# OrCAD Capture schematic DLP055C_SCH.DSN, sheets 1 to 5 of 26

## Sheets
1 P25 - HARDWARE: rev: C
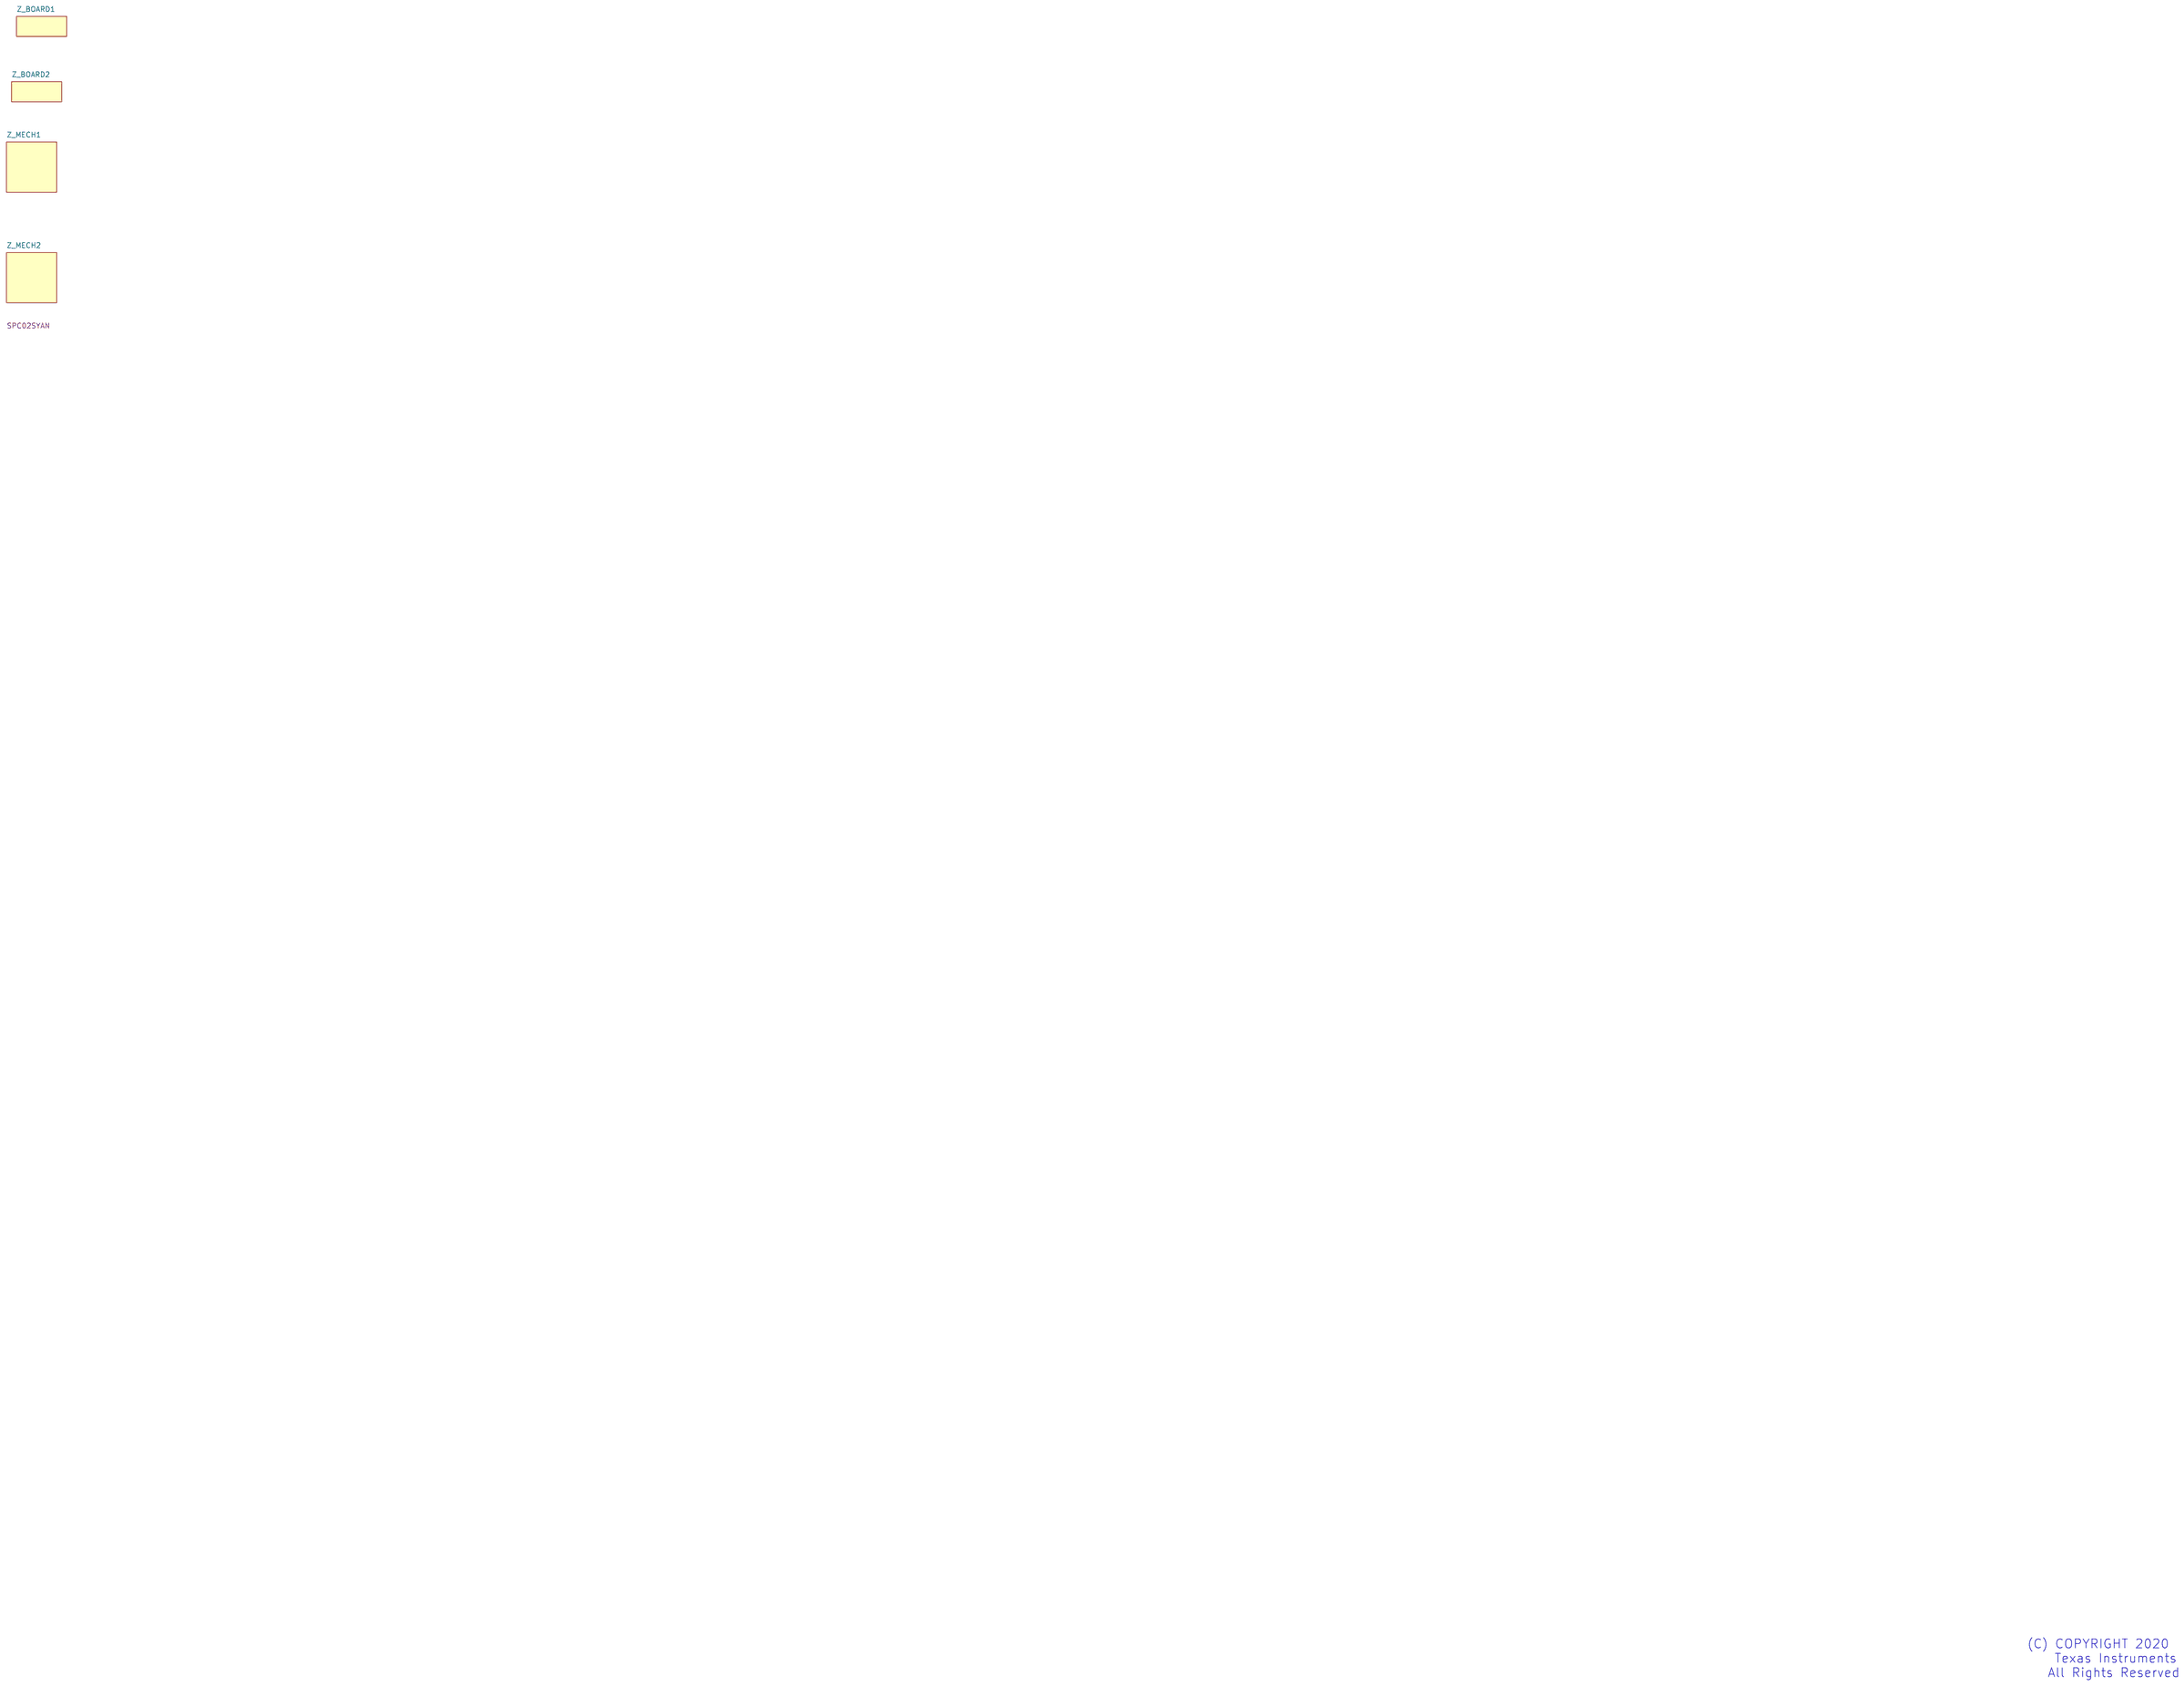
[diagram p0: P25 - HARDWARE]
2 P02 - REVISION HISTORY
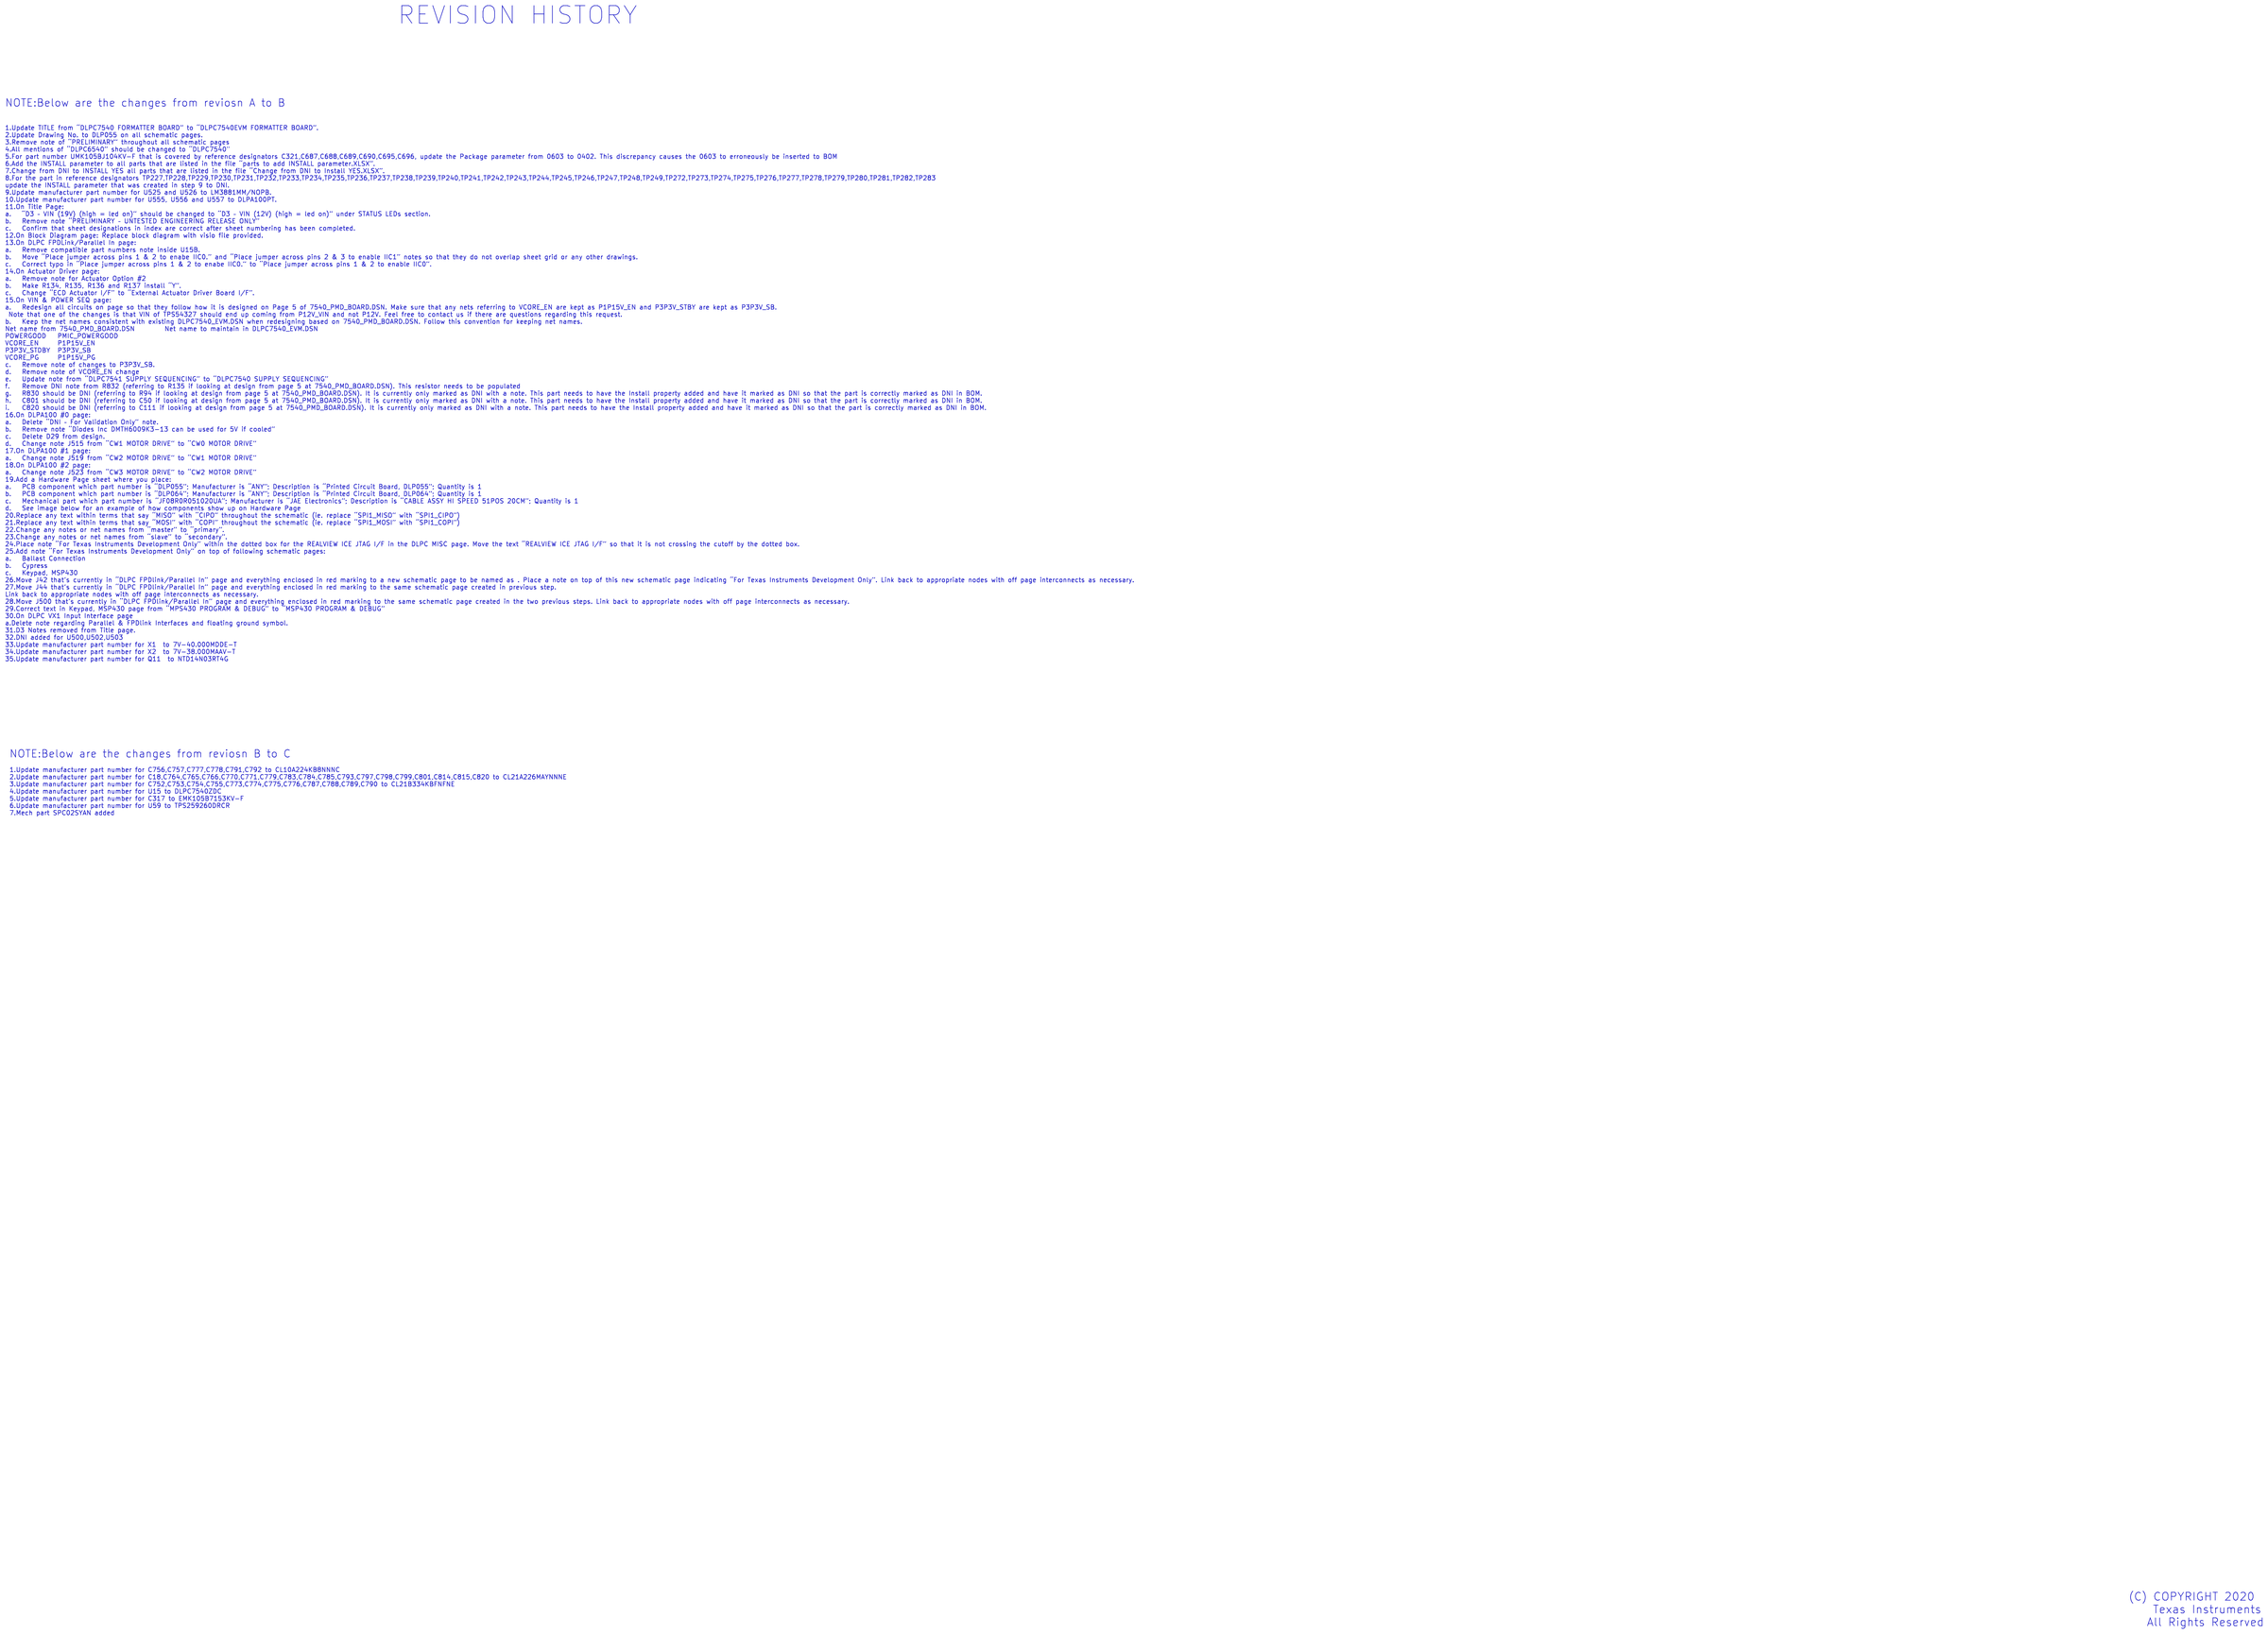
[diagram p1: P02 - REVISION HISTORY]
3 P24-FPDlink-Parallel In Connect: size C
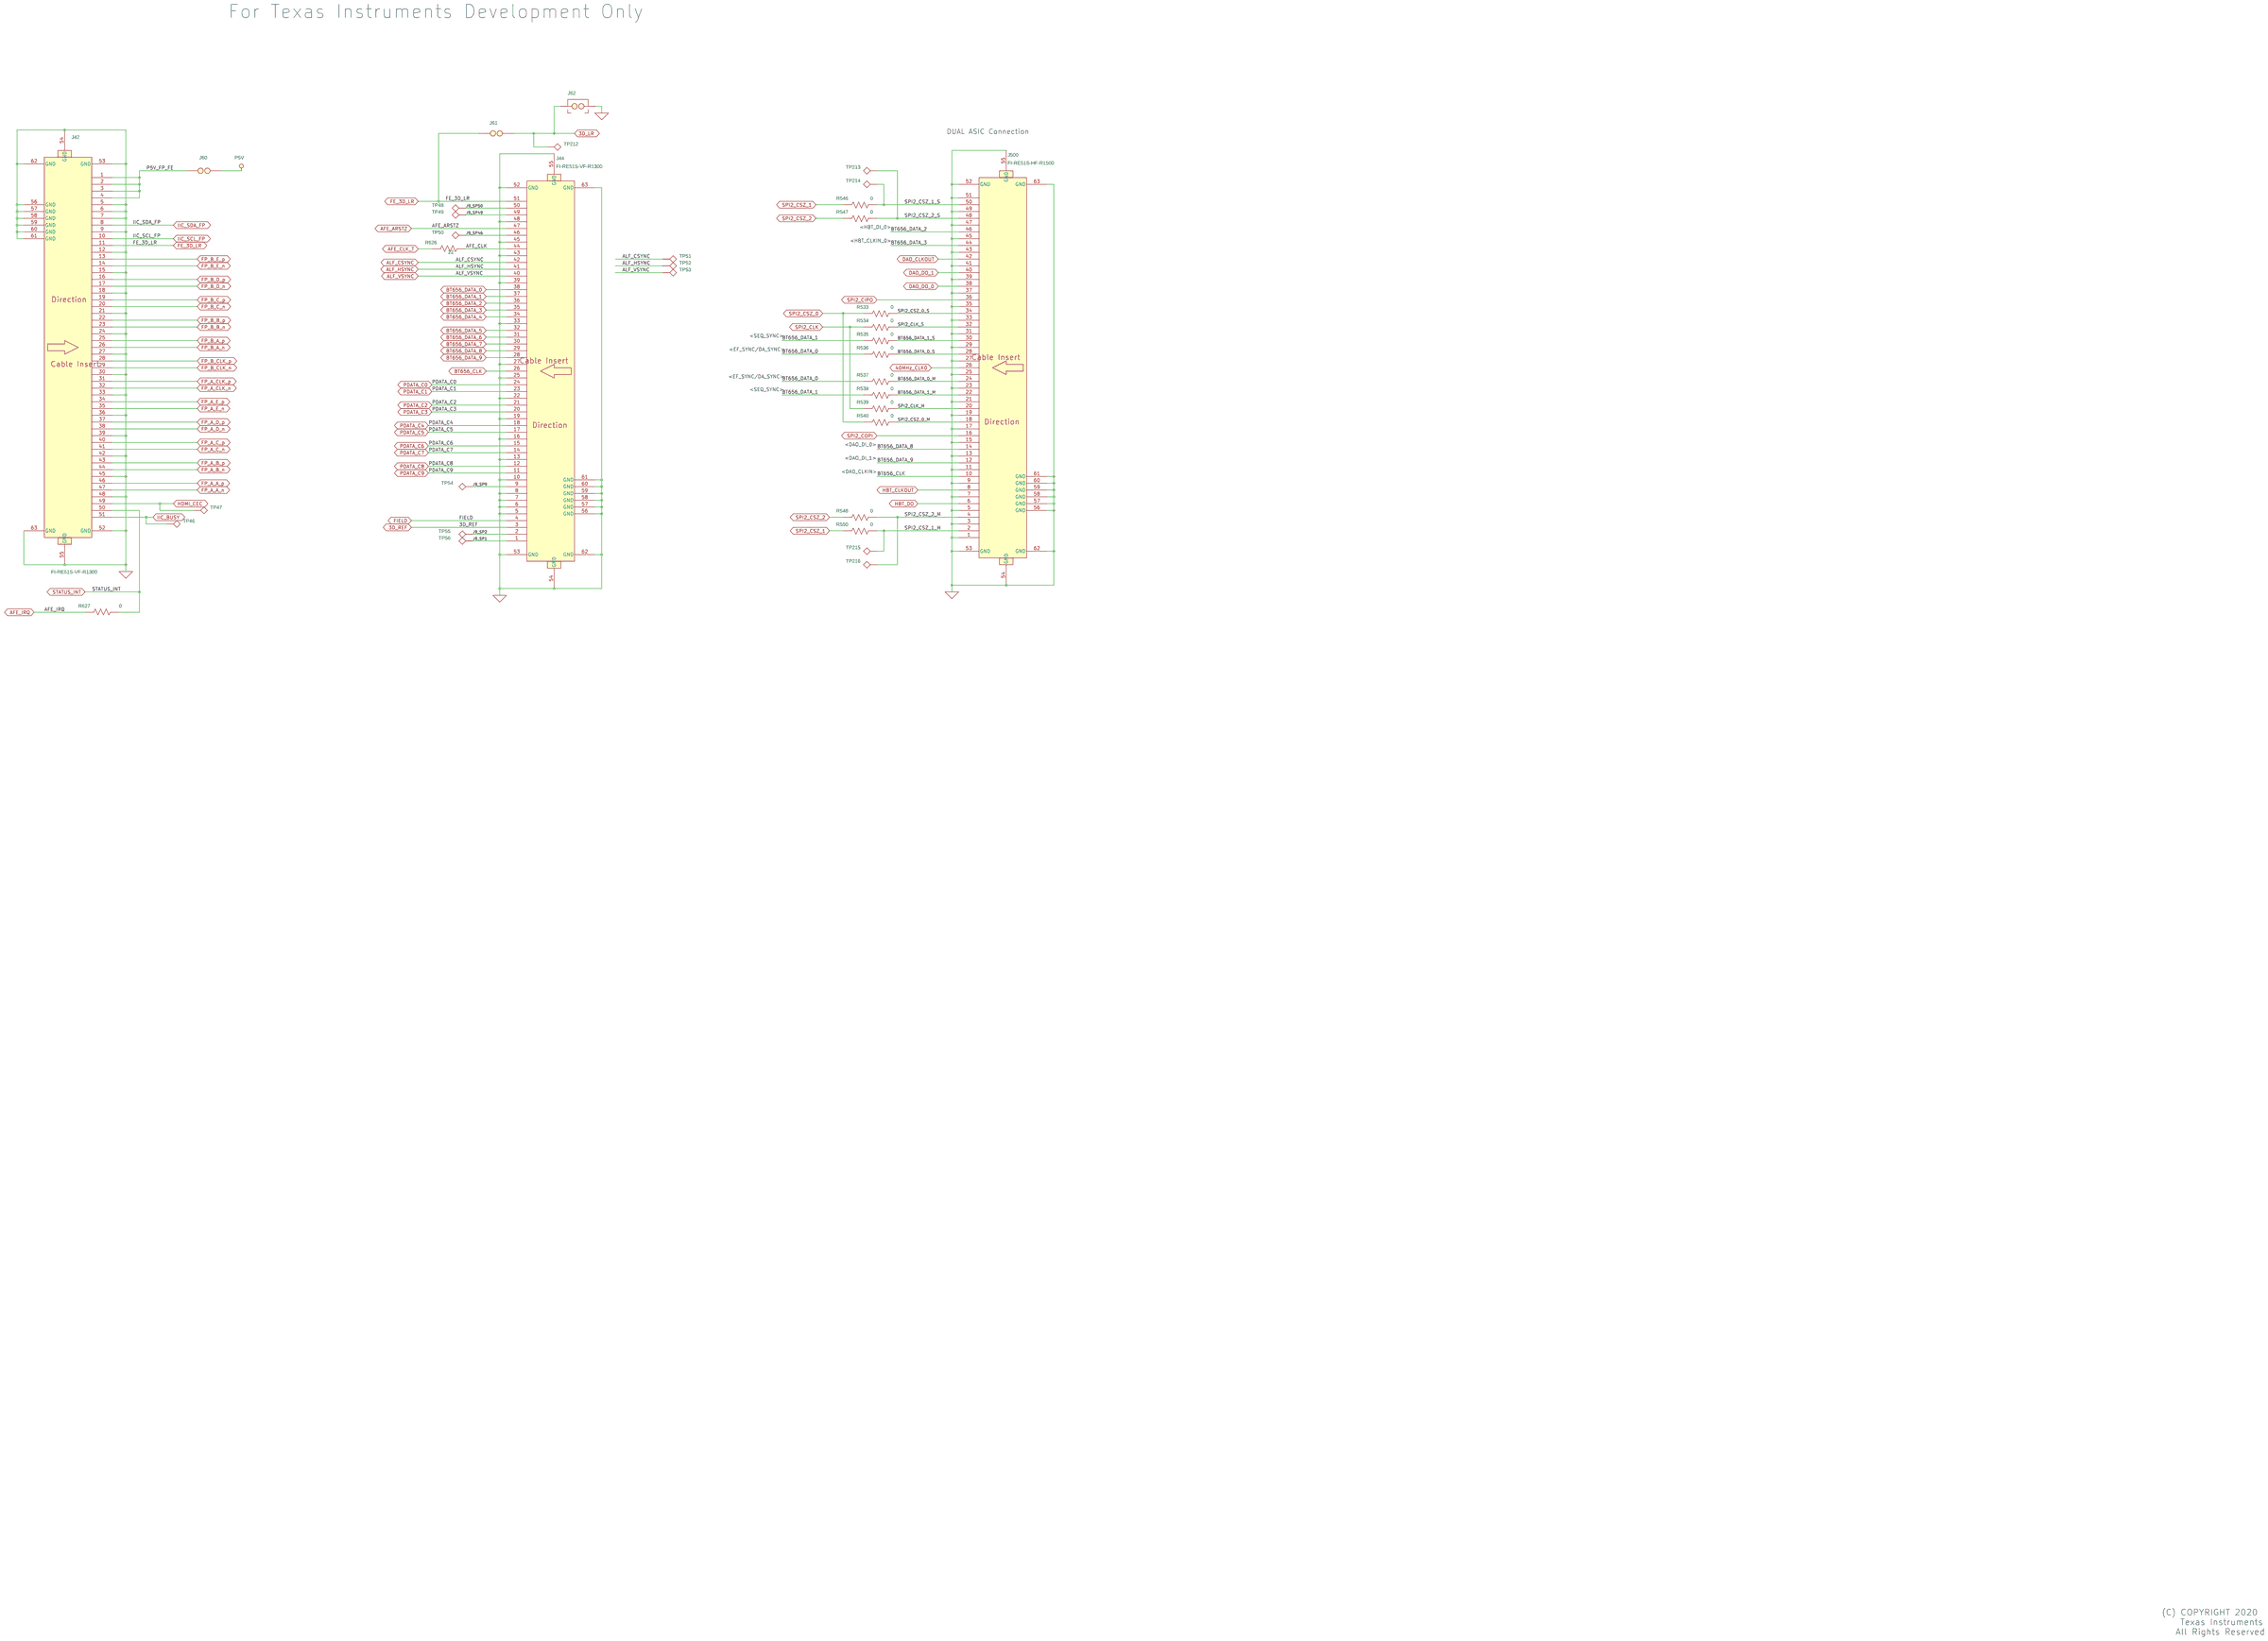
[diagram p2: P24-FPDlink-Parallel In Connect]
4 P22 - Cypress: size A3
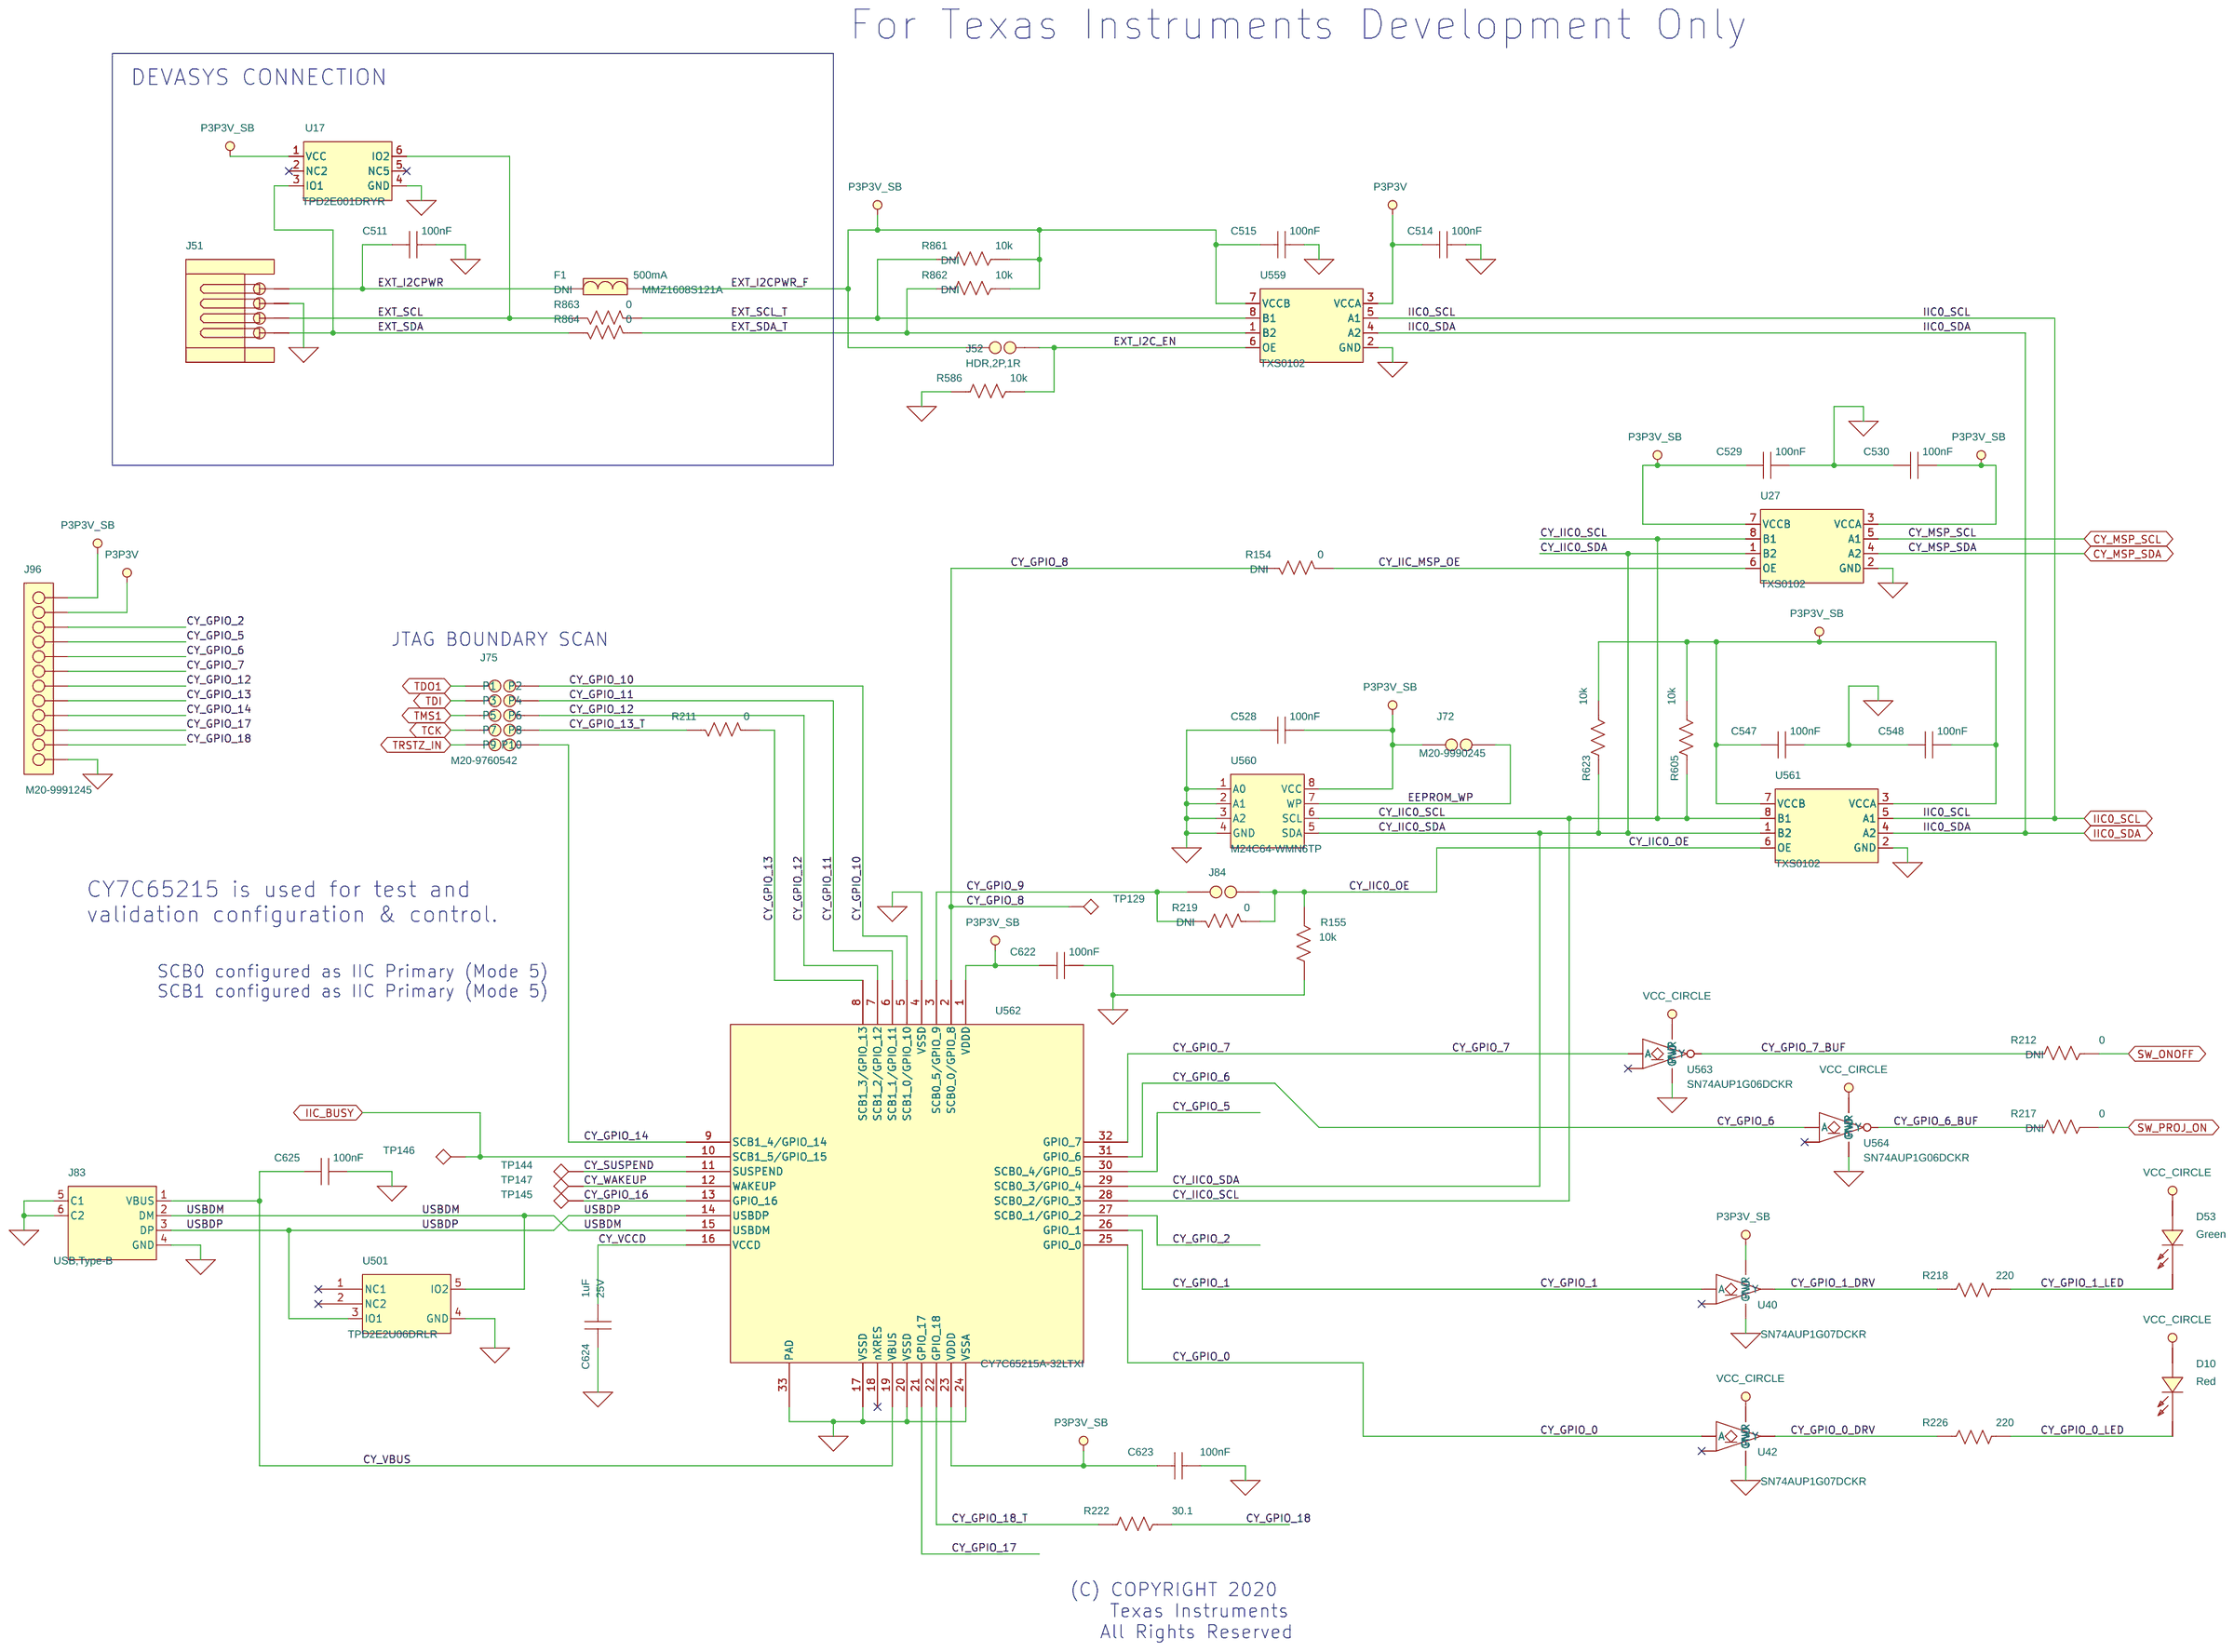
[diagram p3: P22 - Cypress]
5 P23 - Keypad, MSP430: size A3
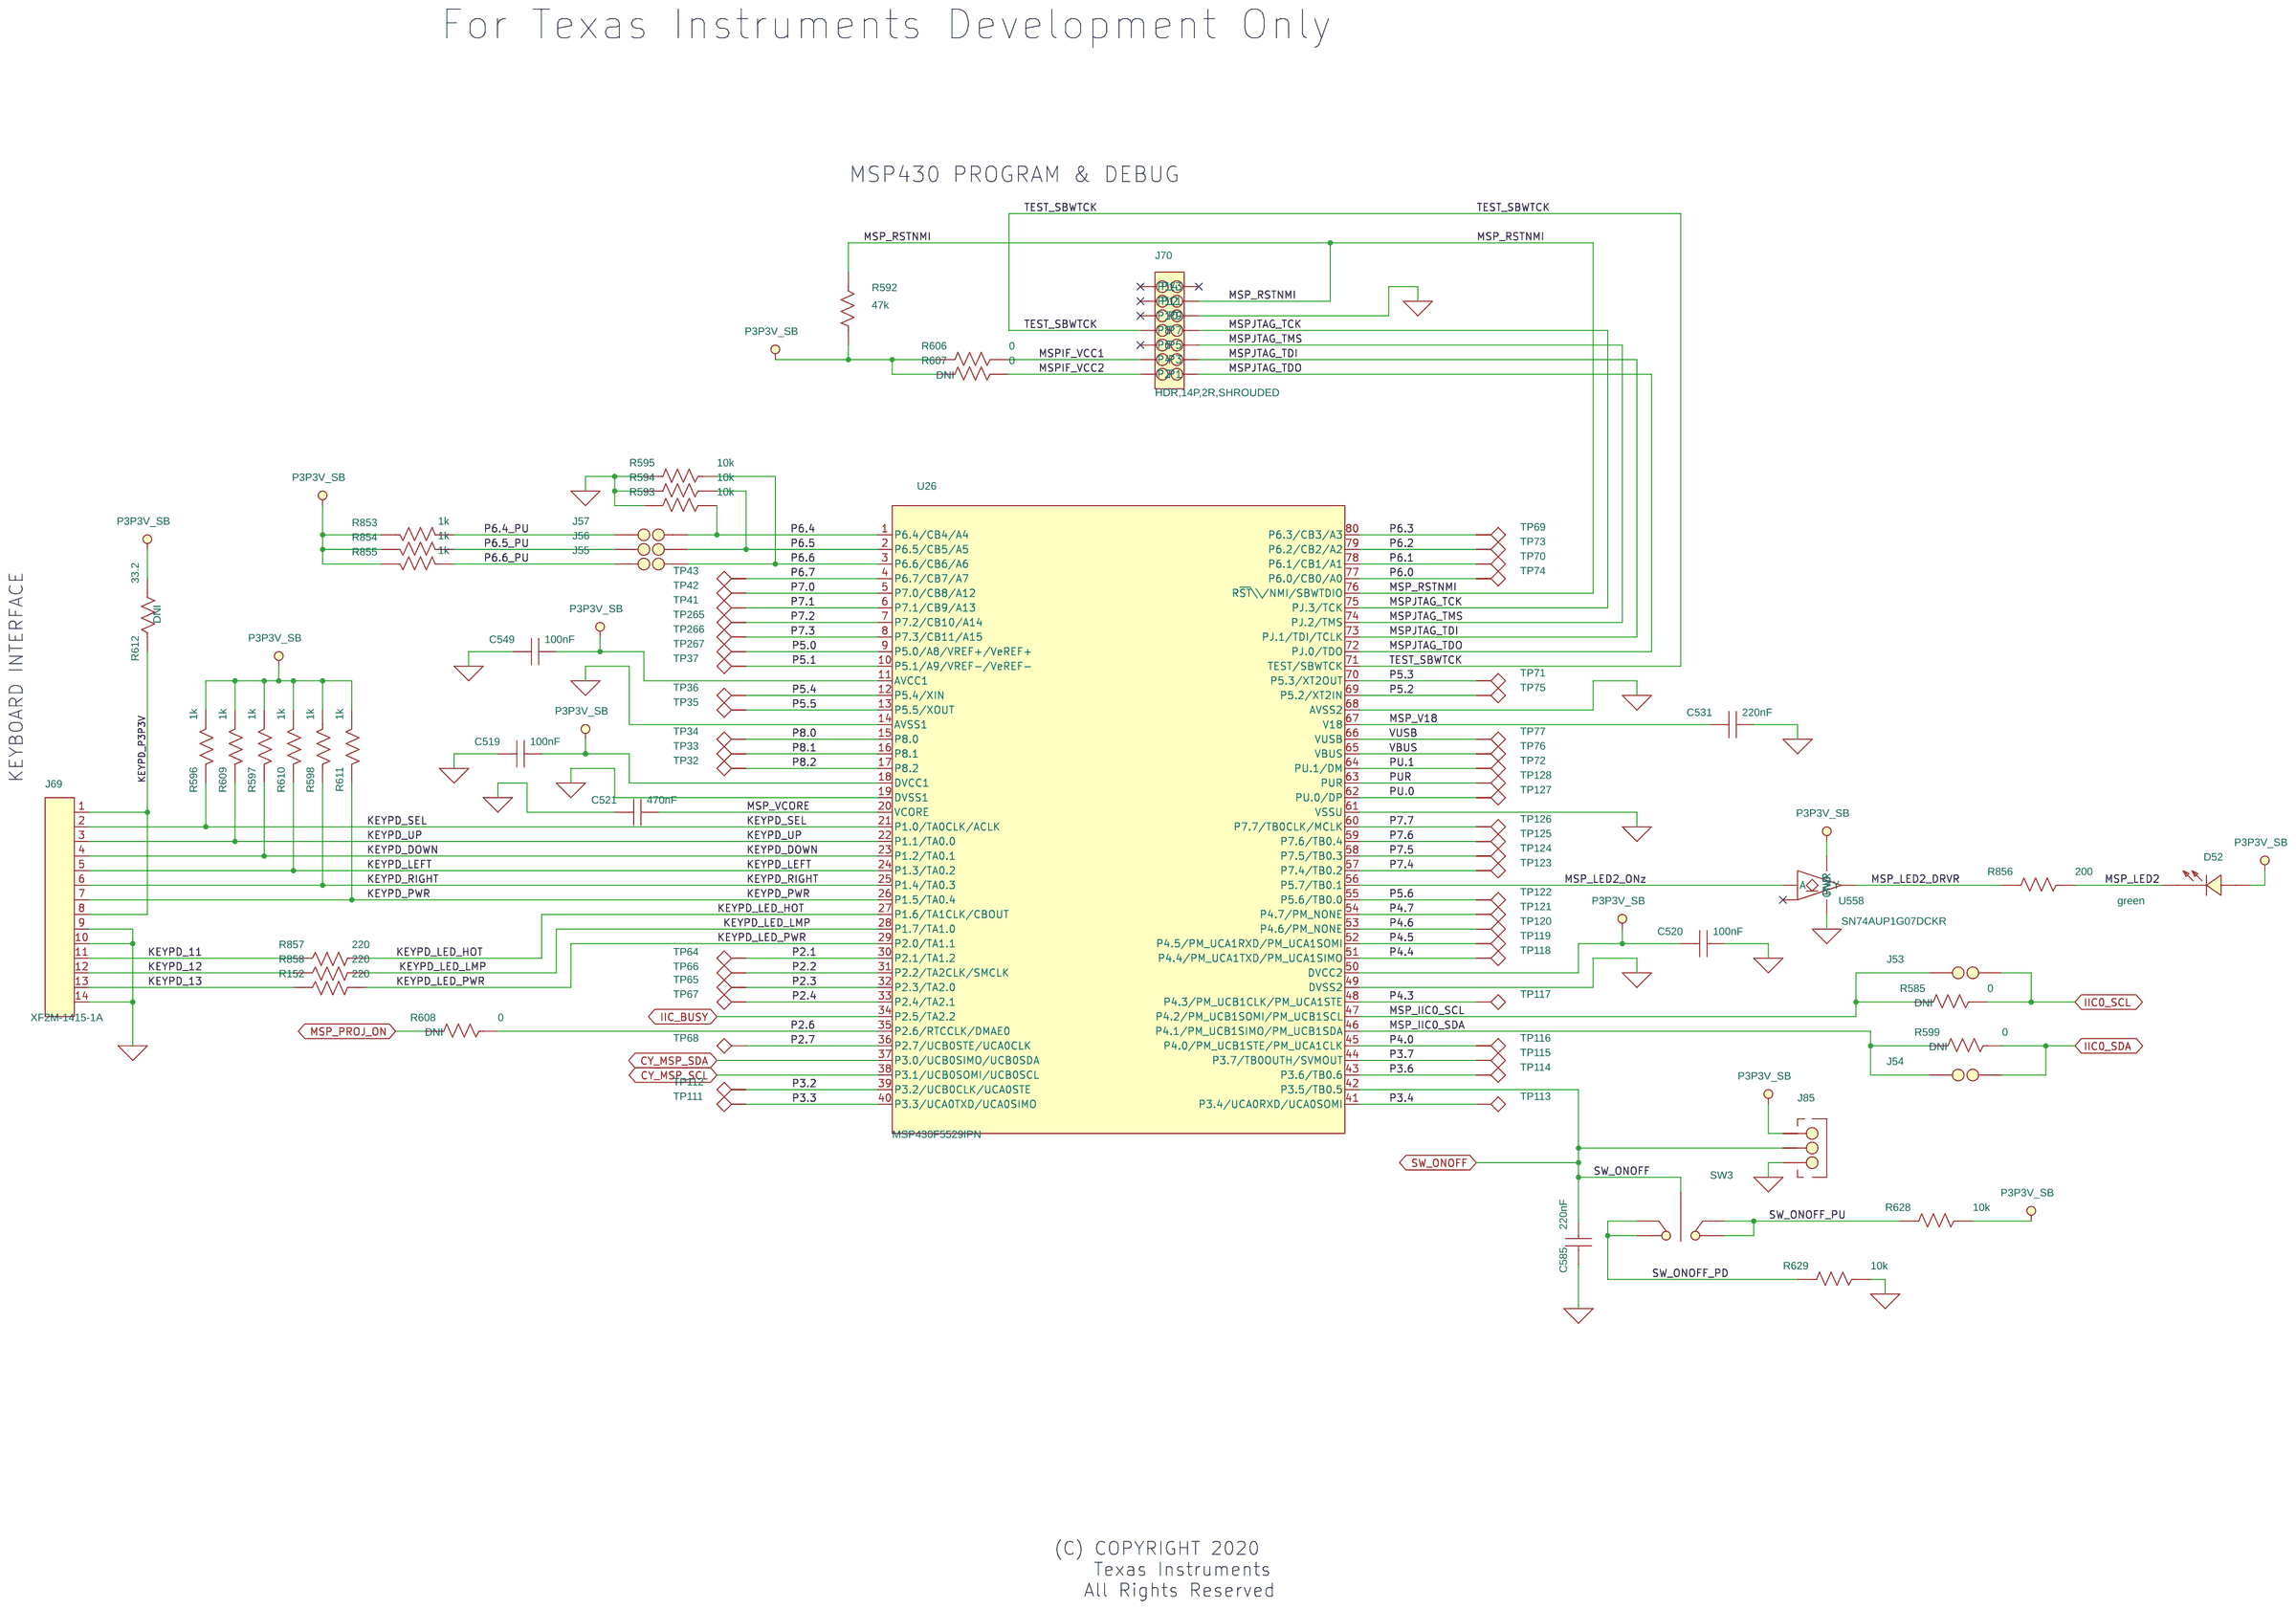
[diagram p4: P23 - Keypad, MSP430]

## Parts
sheet P22 - Cypress
C511  100nF  [0402]
C514  100nF  [0402]
C515  100nF  [0402]
C528  100nF  [0402]
C529  100nF  [0402]
C530  100nF  [0402]
C547  100nF  [0402]
C548  100nF  [0402]
C622  100nF  [0402]
C623  100nF  [0402]
C624  1uF  [0402]
C625  100nF  [0402]
D10  Red  [LED-LTST-C190_LITEON]
D53  Green  [LED-LTST-C190_LITEON]
F1  MMZ1608S121A  [0603]
J51  S4B-EH(LF)(SN)  [CONN4-S4BEH_JST]
J52  HDR,2P,1R  [HDR2P_1R]
J72  HDR,2P,1R  [HDR2P_1R]
J75  HDR,10P,2R  [HDR2X5]
J83  USB,Type-B  [CONN4-USB-897-43-004-90_MILL]
J84  HDR,2P,1R  [HDR2P_1R]
J96  HDR,12P,1R  [HDR1x12]
R154  0  [0402]
R155  10k  [0402]
R211  0  [0402]
R212  0  [0402]
R217  0  [0402]
R218  220  [0603]
R219  0  [0402]
R222  30.1  [0402]
R226  220  [0603]
R586  10k  [0402]
R605  10k  [0402]
R623  10k  [0402]
R861  10k  [0402]
R862  10k  [0402]
R863  0  [0402]
R864  0  [0402]
TP129  TP_WHT  [TP_Keystone_5011]
TP144  TP_WHT  [TP_Keystone_5011]
TP145  TP_WHT  [TP_Keystone_5011]
TP146  TP_WHT  [TP_Keystone_5011]
TP147  TP_WHT  [TP_Keystone_5011]
U17  TPD2E001DRY  [SOIC6-DRY_TI]
U27  TXS0102  [VSSOP-8_DCU]
U40  SN74AUP1G07DCK  [U_5_DCK]
U42  SN74AUP1G07DCK  [U_5_DCK]
U501  TPD2E2U06DRL  [SOT-5_DRL_R-PDSO-N5]
U559  TXS0102  [VSSOP-8_DCU]
U560  M24C64-WMN6TP  [SOIC8-D_TI]
U561  TXS0102  [VSSOP-8_DCU]
U562  CY7C65215A-32LTXI  [QFN32-5X5-A_CYP]
U563  SN74AUP1G06DCK  [U_5_DCK]
U564  SN74AUP1G06DCK  [U_5_DCK]
sheet P23 - Keypad, MSP430
C519  100nF  [0402]
C520  100nF  [0402]
C521  470nF  [0402]
C531  220nF  [0402]
C549  100nF  [0402]
C585  220nF  [0402]
D52  green  [LED-1206]
J53  HDR,2P,1R  [HDR2P_1R]
J54  HDR,2P,1R  [HDR2P_1R]
J55  HDR,2P,1R  [HDR2P_1R]
J56  HDR,2P,1R  [HDR2P_1R]
J57  HDR,2P,1R  [HDR2P_1R]
J69  XF2M-1415-1A  [CONN14-XF2M-REV-A_OMRON]
J70  HDR,14P,2R,SHROUDED  [HDR7X2-5103308_TYCO]
J85  B3B-EH  [CONN3-B3B-EH_JST]
R152  220  [0603]
R585  0  [0402]
R592  47k  [0402]
R593  10k  [0402]
R594  10k  [0402]
R595  10k  [0402]
R596  1k  [0402]
R597  1k  [0402]
R598  1k  [0402]
R599  0  [0402]
R606  0  [0402]
R607  0  [0402]
R608  0  [0402]
R609  1k  [0402]
R610  1k  [0402]
R611  1k  [0402]
R612  33.2  [0402]
R628  10k  [0402]
R629  10k  [0402]
R853  1k  [0402]
R854  1k  [0402]
R855  1k  [0402]
R856  200  [0402]
R857  220  [0603]
R858  220  [0603]
SW3  GT11MSCBE  [GT11MSCBE]
TP32  TP,20mil PAD  [20mil_PAD]
TP33  TP,20mil PAD  [20mil_PAD]
TP34  TP,20mil PAD  [20mil_PAD]
TP35  TP,20mil PAD  [20mil_PAD]
TP36  TP,20mil PAD  [20mil_PAD]
TP37  TP,20mil PAD  [20mil_PAD]
TP41  TP,20mil PAD  [20mil_PAD]
TP42  TP,20mil PAD  [20mil_PAD]
TP43  TP,20mil PAD  [20mil_PAD]
TP64  TP,20mil PAD  [20mil_PAD]
TP65  TP,20mil PAD  [20mil_PAD]
TP66  TP,20mil PAD  [20mil_PAD]
TP67  TP,20mil PAD  [20mil_PAD]
TP68  TP,20mil PAD  [20mil_PAD]
TP69  TP,20mil PAD  [20mil_PAD]
TP70  TP,20mil PAD  [20mil_PAD]
TP71  TP,20mil PAD  [20mil_PAD]
TP72  TP,20mil PAD  [20mil_PAD]
TP73  TP,20mil PAD  [20mil_PAD]
TP74  TP,20mil PAD  [20mil_PAD]
TP75  TP,20mil PAD  [20mil_PAD]
TP76  TP,20mil PAD  [20mil_PAD]
TP77  TP,40mil Drill,60mil Pad  [TP-60RD40]
TP111  TP,20mil PAD  [20mil_PAD]
TP112  TP,20mil PAD  [20mil_PAD]
TP113  TP,20mil PAD  [20mil_PAD]
TP114  TP,20mil PAD  [20mil_PAD]
TP115  TP,20mil PAD  [20mil_PAD]
TP116  TP,20mil PAD  [20mil_PAD]
TP117  TP,20mil PAD  [20mil_PAD]
TP118  TP,20mil PAD  [20mil_PAD]
TP119  TP,20mil PAD  [20mil_PAD]
TP120  TP,20mil PAD  [20mil_PAD]
TP121  TP,20mil PAD  [20mil_PAD]
TP122  TP,20mil PAD  [20mil_PAD]
TP123  TP,20mil PAD  [20mil_PAD]
TP124  TP,20mil PAD  [20mil_PAD]
TP125  TP,20mil PAD  [20mil_PAD]
TP126  TP,20mil PAD  [20mil_PAD]
TP127  TP,20mil PAD  [20mil_PAD]
TP128  TP,20mil PAD  [20mil_PAD]
TP265  TP,20mil PAD  [20mil_PAD]
TP266  TP,20mil PAD  [20mil_PAD]
TP267  TP,20mil PAD  [20mil_PAD]
U26  MSP430F5529IPN  [PQFP80-PN_TI]
U558  SN74AUP1G07DCK  [U_5_DCK]
sheet P24-FPDlink-Parallel In Connect
J42  FI-RE51S-VF-R1300  [FI-R51-HF_VF_Dual]
J44  FI-RE51S-VF-R1300  [FI-R51-HF_VF_Dual]
J60  HDR,2P,1R  [HDR2P_1R]
J61  HDR,2P,1R  [HDR2P_1R]
J62  B2B-EH  [JST_B2B-EH]
J500  FI-RE51S-HF-R1500  [FI-R51-HF_VF_Dual]
R533  0  [0402]
R534  0  [0402]
R535  0  [0402]
R536  0  [0402]
R537  0  [0402]
R538  0  [0402]
R539  0  [0402]
R540  0  [0402]
R546  0  [0402]
R547  0  [0402]
R548  0  [0402]
R550  0  [0402]
R626  22  [0402]
R627  0  [0402]
TP46  TP,28mil Drill,48mil Pad  [HTP-48RD28]
TP47  TP,28mil Drill,48mil Pad  [HTP-48RD28]
TP48  TP,28mil Drill,48mil Pad  [HTP-48RD28]
TP49  TP,28mil Drill,48mil Pad  [HTP-48RD28]
TP50  TP,28mil Drill,48mil Pad  [HTP-48RD28]
TP51  TP,28mil Drill,48mil Pad  [HTP-48RD28]
TP52  TP,28mil Drill,48mil Pad  [HTP-48RD28]
TP53  TP,28mil Drill,48mil Pad  [HTP-48RD28]
TP54  TP,28mil Drill,48mil Pad  [HTP-48RD28]
TP55  TP,28mil Drill,48mil Pad  [HTP-48RD28]
TP56  TP,28mil Drill,48mil Pad  [HTP-48RD28]
TP212  TP,28mil Drill,48mil Pad  [HTP-48RD28]
TP213  TP,28mil Drill,48mil Pad  [HTP-48RD28]
TP214  TP,28mil Drill,48mil Pad  [HTP-48RD28]
TP215  TP,28mil Drill,48mil Pad  [HTP-48RD28]
TP216  TP,28mil Drill,48mil Pad  [HTP-48RD28]
sheet P25 - HARDWARE
Z_BOARD1  DLP055
Z_BOARD2  DLP064
Z_MECH1  JF08R0R051020UA
Z_MECH2  SPC02SYAN

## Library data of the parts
C511 C514 C515 = PAS,CAP,NP: ALT_SYMBOLS: 0402_1mm; DigiKey: 1276-1001-1-ND; Family: passive; Index PN: 681; Lead Style: SMT; MFG: Samsung; Material: x7r; P/D_NUM: CL05B104KO5NNNC; Part Number: CL05B104KO5NNNC; Part Specific: CAP CER .1UF 16V X7R 0402; VPC: 16V; Vendor: Samsung
C528-C530 C547 C548 C622 C623 C625 = PAS,CAP,NP: ALT_SYMBOLS: 0402_1mm; DigiKey: 1276-1001-1-ND; Family: passive; Index PN: 681; Lead Style: SMT; MFG: Samsung; Material: x7r; P/D_NUM: CL05B104KO5NNNC; Part Number: CL05B104KO5NNNC; Part Specific: CAP CER .1UF 16V X7R 0402; TOLERANCE: 10%; Type: capacitor; VENDOR: Samsung; VPC: 16V
C624 = PAS,CAP,NP: ALT_SYMBOLS: 0402_1mm; DigiKey: 1276-1445-1-ND; Family: passive; Index PN: 916; Lead Style: SMT; MFG: Samsung; Material: x5r; P/D_NUM: CL05A105KA5NQNC; Part Number: CL05A105KA5NQNC; Part Specific: CAP CER 1UF 25V X5R 0402; TOLERANCE: 10%; Type: capacitor; VENDOR: Samsung; VPC: 25V
D10 = PAS,DIODE,LED,ALT: DigiKey: 160-1447-1-ND; Family: passive; Index PN: 1452; Install: Y; Lead Style: SMT; MFG: Liteon; P/D_NUM: LTST-C191KRKT; Part Number: LTST-C191KRKT; Part Specific: LED RED CLEAR 0603 SMD; Type: diode,led; Vendor: Liteon
D53 = PAS,DIODE,LED,ALT: DigiKey: 160-1183-1-ND; Family: passive; Index PN: 1451; Install: Y; Lead Style: SMT; MFG: Liteon; P/D_NUM: LTST-C190GKT; Part Number: LTST-C190GKT; Part Specific: LED GREEN CLEAR 0603 SMD; Type: diode,led; Vendor: Liteon
F1 = PAS,FERRITE_BEAD,3: DigiKey: 445-2173-1-ND; Family: passive; Index PN: 1141; Install: DNI; Lead Style: SMT; MFG: TDK; Part Specific: FERRITE CHIP 120 OHM 500MA 06; Type: ferrite bead; VENDOR: TDK; VPC: 500mA
J51 = EM,CONN,4P,EH,Devasys,1x: DigiKey: 455-1627-ND; Family: electro/mechanical; Index PN: 1005; Lead Style: TH; MFG: JST; Part Specific: CONN HEADER EH SIDE 4POS 2.5MM; Type: connector
J52 J60 J72 J84 = EM,JMP,2P,1R: DigiKey: 952-2261-ND; Index PN: 180; Lead Style: TH; MFG: Harwin; P/D_NUM: M20-9990245; Part Number: M20-9990245; Part Specific: 2 Positions Header  Unshrouded  Breakaway Connector 0.100in (2.54mm) Through Hole Gold; Pin Cnt: 2; Pin Spacing: 100mil; Row Cnt: 1; Type: header; Vendor: Harwin
J75 = EM,JMP,10P,2R,1x: DigiKey: 952-2117-ND; Family: electro/mechanical; Index PN: 17; Lead Style: TH; MFG: Harwin; P/D_NUM: M20-9760542; Part Number: M20-9760542; Part Specific: CONN HEADER 10POS .100in DL GOLD; Pin Cnt: 10; Pin Spacing: 100x100mil; Row Cnt: 2; Type: header; Vendor: Harwin
J83 = EM,CONN,USB,TYPE-B: DigiKey: ED90064-ND; Family: electro/mechanical; Index PN: 731; Install: Y; Lead Style: TH; MFG: mill-max; P/D_NUM: 897-43-004-90-000000; Part Number: 897-43-004-90-000000; Part Specific: CONN RECEPT USB TYPE B PCB; Type: connector; Vendor: mill-max
J96 = EM,HDR,12P,1R,1x: DigiKey: 952-3302-ND; Family: electro/mechanical; Index PN: 165; Install: Y; Lead Style: TH; MFG: Harwin; P/D_NUM: M20-9991245; Part Number: M20-9991245; Part Specific: CONN HEADER VERT 12POS 2.54MM; Pin Cnt: 12; Pin Spacing: 100mil; Row Cnt: 1; Type: header; Vendor: Harwin
R154 R212 R217 R219 R585 R599 R607 R608 = PAS,R,large: ALT_SYMBOLS: 0402_1mm; DigiKey: P0.0JCT-ND; Family: passive; Index PN: 687; Install: DNI; Lead Style: SMT; MFG: Panasonic; Material: chip; P/D_NUM: ERJ-2GE0R00X; Part Number: ERJ-2GE0R00X; Part Specific: RES 0.0 OHM 1/16W 0402 SMD; Power: 1/16W; Type: resistor; VPC: 1/16W; Vendor: Panasonic
R155 R593-R595 R628 R629 = PAS,R,large: ALT_SYMBOLS: 0402_1mm; DigiKey: 311-10.0KLRCT-ND; Family: passive; Index PN: 680; Lead Style: SMT; MFG: Yageo; Material: chip; P/D_NUM: RC0402FR-0710KL; Part Number: RC0402FR-0710KL; Power: 1/16W; Tolerance: 1%; Type: resistor; VPC: 1/16W; Vendor: Yageo
R211 R627 = PAS,R,large: ALT_SYMBOLS: 0402_1mm; DigiKey: P0.0JCT-ND; Family: passive; Index PN: 687; Install: Y; Lead Style: SMT; MFG: Panasonic; Material: chip; P/D_NUM: ERJ-2GE0R00X; Part Number: ERJ-2GE0R00X; Part Specific: RES 0.0 OHM 1/16W 0402 SMD; Power: 1/16W; Type: resistor; VPC: 1/16W; Vendor: Panasonic
R152 R218 R226 R857 R858 = PAS,R,large: CCA: 95; DigiKey: P220BYCT-ND; Family: passive; ICA_MFR_NAME: PANASONIC; ICA_PARTNUM: $$1785048$$ERJ-3GSYJ102; Index PN: 1420; Install: Y; Lead Style: SMT; MFG: Panasonic; Material: chip; P/D_NUM: ERJ-PA3F2200V; Part Number: ERJ-PA3F2200V; Part Specific: RES SMD 220 OHM 1% 1/4W 0603; TOLERANCE: 1%; Type: resistor; VPC: 1/10W; Vendor: Panasonic
R222 = PAS,R,large: ALT_SYMBOLS: 0402_1mm; DigiKey: YAG3111CT-ND; Family: passive; Index PN: 976; Install: Y; Lead Style: SMT; MFG: Yageo; Material: chip; P/D_NUM: RC0402FR-0730R1L; Part Number: RC0402FR-0730R1L; Part Specific: RES 30.1 OHM 1/16W 1% 0402 SMD; Power: 1/16W; Tolerance: 1%; Type: resistor; VPC: 1/16W; Vendor: Yageo
R586 = PAS,R,large: ALT_SYMBOLS: 0402_1mm; DigiKey: 311-10.0KLRCT-ND; Family: passive; Index PN: 680; Install: Y; Lead Style: SMT; MFG: Yageo; Material: chip; P/D_NUM: RC0402FR-0710KL; Part Number: RC0402FR-0710KL; Power: 1/16W; TOLERANCE: 1%; Type: resistor; VENDOR: Yageo; VPC: 1/16W
R605 R623 = PAS,R,large: ALT_SYMBOLS: 0402_1mm; DigiKey: 311-10.0KLRCT-ND; Family: passive; Index PN: 680; Install: Y; Lead Style: SMT; MFG: Yageo; Material: chip; P/D_NUM: RC0402FR-0710KL; Part Number: RC0402FR-0710KL; Power: 1/16W; Tolerance: 1%; Type: resistor; VPC: 1/16W; Vendor: Yageo
R861 R862 = PAS,R,large: ALT_SYMBOLS: 0402_1mm; DigiKey: 311-10.0KLRCT-ND; Family: passive; Index PN: 680; Install: DNI; Lead Style: SMT; MFG: Yageo; Material: chip; P/D_NUM: RC0402FR-0710KL; Part Number: RC0402FR-0710KL; Power: 1/16W; TOLERANCE: 1%; Type: resistor; VENDOR: Yageo; VPC: 1/16W
R606 R863 R864 = PAS,R,large: ALT_SYMBOLS: 0402_1mm; DigiKey: P0.0JCT-ND; Family: passive; Index PN: 687; Lead Style: SMT; MFG: Panasonic; Material: chip; P/D_NUM: ERJ-2GE0R00X; Part Number: ERJ-2GE0R00X; Part Specific: RES 0.0 OHM 1/16W 0402 SMD; Power: 1/16W; Type: resistor; VPC: 1/16W; Vendor: Panasonic
TP129 TP144-TP147 = EM,TERM,TESTPOINT: DigiKey: 36-5012-ND; Family: electro/mechanical; Index PN: 1162; Install: DNI; Lead Style: TH; MFG: Keystone; P/D_NUM: 5012; Part Number: 5012; Part Specific: TEST POINT PC MULTI PURPOSE WHT .063inD hole; Type: terminal; Vendor: Keystone
U17 = PAS,DIODE,TVS,TPD2E001DRY,1x: DigiKey: 296-21884-1-ND; Family: passive; Index PN: 1029; Lead Style: SMT; MFG: Texas Instruments; P/D_NUM: TPD2E001DRYR; Part Number: TPD2E001DRYR; Part Specific: IC ESD-PROT ARRAY 2CH 6-SON; Type: diode,tvs
U27 U559 U561 = INF,DRVR,I2C,TXS0102,1x: DigiKey: 296-21931-1-ND; Family: interface; Index PN: 877; Lead Style: SMT; MFG: Texas Instruments; P/D_NUM: TXS0102DCU; Part Number: TXS0102DCU; Part Specific: IC VOLT-LEVEL TRANSLATOR 8-US8; Type: driver; Vendor: Texas Instruments
U40 = TMP_27: DigiKey: 296-18256-1-ND; Family: logic; Index PN: 1027; Lead Style: SMT; MFG: Texas Instruments; P/D_NUM: SN74AUP1G07DCKR; Part Number: SN74AUP1G07DCKR; Part Specific: IC BUFF/DVR LOW PWR N-INV SC705  open drain; Type: buffer
U42 = TMP_28: DigiKey: 296-18256-1-ND; Family: logic; Index PN: 1027; Lead Style: SMT; MFG: Texas Instruments; P/D_NUM: SN74AUP1G07DCKR; Part Number: SN74AUP1G07DCKR; Part Specific: IC BUFF/DVR LOW PWR N-INV SC705  open drain; Type: buffer
U501 = PAS,DIODE,TVS,TPD2E2U06DRL,1x: DigiKey: 296-38361-1-ND; Family: passive; Index PN: 1340; Lead Style: SMT; MFG: Texas Instruments; P/D_NUM: TPD2E2U06DRLR; Part Number: TPD2E2U06DRLR; Part Specific: TVS DIODE 5.5VWM 12.4VC 5SOT; Type: diode,tvs
U560 = MEM,EEPROM,24LCxx: DigiKey: 497-8650-1-ND; Family: memory; Index PN: 1729; Install: Y; Lead Style: SMT; MFG: STMicroelectronics; Part Specific: IC EEPROM 64K I2C 1MHZ 8SO; Type: eeprom; Vendor: STMicroelectronics
U562 = INF,USB2SERIAL,CY7C65215,1x: DigiKey: 428-3664-ND; Family: interface; Index PN: 1650; Lead Style: SMT; MFG: Cypress; Part Specific: IC USB TO UART/I2C/SPI 32QFN; Type: usb; Vendor: Cypress
U563 = TMP_25: DigiKey: 296-17562-1-ND; Family: logic; Index PN: 1026; Lead Style: SMT; MFG: Texas Instruments; P/D_NUM: SN74AUP1G06DCKR; Part Number: SN74AUP1G06DCKR; Part Specific: IC INVERTER SINGLE 1INPUT SC705  open drain; Type: buffer
U564 = TMP_26: DigiKey: 296-17562-1-ND; Family: logic; Index PN: 1026; Lead Style: SMT; MFG: Texas Instruments; P/D_NUM: SN74AUP1G06DCKR; Part Number: SN74AUP1G06DCKR; Part Specific: IC INVERTER SINGLE 1INPUT SC705  open drain; Type: buffer
C519 C520 C549 = CER_0.1UF_16V_10%_X5R_0402: ALT_SYMBOLS: 0402_1mm; CCA: 34; DigiKey: 587-3499-1-ND; Family: passive; Index PN: 1280; Install: Y; Lead Style: SMT; MFG: Taiyo Yuden; Material: x5r; P/D_NUM: UMK105BJ104KV-F; Part Number: UMK105BJ104KV-F; Part Specific: CAP CER 0.1UF 50V 10% X5R 0402; Type: capacitor; VPC: 50V; Vendor: Taiyo Yuden
C521 = CER_0.1UF_16V_10%_X5R_0402: ALT_SYMBOLS: 0402_1mm; CCA: 34; DigiKey: 587-3497-1-ND; Family: passive; Index PN: 1284; Install: Y; Lead Style: SMT; MFG: Taiyo Yuden; P/D_NUM: UMK105ABJ474KV-F; Part Number: UMK105ABJ474KV-F; Part Specific: CAP CER 0.47UF 50V X5R 0402; Type: capacitor; VPC: 50V; Vendor: Taiyo Yuden
C531 C585 = CER_0.1UF_16V_10%_X5R_0402: ALT_SYMBOLS: 0402_1mm; CCA: 34; DigiKey: 587-2475-1-ND; Family: passive; Index PN: 905; Install: Y; Lead Style: SMT; MFG: Taiyo Yuden; Material: x7r; P/D_NUM: JMK105B7224KV-F; Part Number: JMK105B7224KV-F; Part Specific: CAP CER .22UF 6.3V X7R 10% 0402; Type: capacitor; VPC: 6.3V; Vendor: Taiyo Yuden
D52 = PAS,DIODE,LED,ALT: DigiKey: 67-1357-1-ND; Family: passive; Index PN: 31; Lead Style: SMT; MFG: Lumex; P/D_NUM: SML-LX1206GC-TR; Part Number: SML-LX1206GC-TR; Part Specific: LED 565NM WTR CLR GREEN 1206 SMD; Type: diode,led; Vendor: Lumex
J53-J57 J61 = EM,JMP,2P,1R: DigiKey: 952-2261-ND; Family: electro/mechanical; Index PN: 180; Install: Y; Lead Style: TH; MFG: Harwin; P/D_NUM: M20-9990245; Part Number: M20-9990245; Part Specific: 2 Positions Header  Unshrouded  Breakaway Connector 0.100in (2.54mm) Through Hole Gold; Pin Cnt: 2; Pin Spacing: 100mil; Row Cnt: 1; Type: header; VENDOR: Harwin
J69 = EM,HDR,14P,1R: DigiKey: OR755CT-ND; Family: electro/mechanical; Index PN: 1526; Install: Y; Lead Style: SMT; MFG: Omron; Part Specific: CONN FPC 14POS 0.50MM R/A; Pin Cnt: 14; Pin Spacing: .5mm; Row Cnt: 1; Type: connector; Vendor: Omron
J70 = EM,HDR,14P,2R,1X,Narrow: DigiKey: A33161-ND; Family: electro/mechanical; Index PN: 978; Install: Y; Lead Style: TH; MFG: Tyco Electronics; P/D_NUM: 5103308-2; Part Number: 5103308-2; Part Specific: CONN HEADER LOPRO STR 14POS GOLD; Pin Cnt: 14; Pin Spacing: 100x100mil; Row Cnt: 2; Type: header; Vendor: Tyco Electronics
J85 = EM,HDR,3P,1R,1x,B3B-EH: DigiKey: 455-1612-ND; Family: electro/mechanical; Index PN: 1291; Lead Style: TH; MFG: JST; P/D_NUM: B3B-EH-A(LF)(SN); Part Number: B3B-EH-A(LF)(SN); Part Specific: CONN HEADER EH TOP 3POS 2.5MM; Pin Cnt: 3; Pin Spacing: 2.5MM; Row Cnt: 1; Type: header; Vendor: JST
R592 = PAS,R,large: ALT_SYMBOLS: 0402_1mm; DigiKey: P47.0KLCT-ND; Family: passive; Index PN: 1030; Lead Style: SMT; MFG: Panasonic; Material: chip; P/D_NUM: ERJ-2RKF4702X; Part Number: ERJ-2RKF4702X; Part Specific: RES 47.0K OHM 1/10W 1% 0402 SMD; Type: resistor; VPC: 1/16W; Vendor: Panasonic
R596-R598 R609-R611 R853-R855 = PAS,R,large: ALT_SYMBOLS: 0402_1mm; CCA: 64; DigiKey: 311-1.00KLRCT-ND; Family: passive; ICA_MFR_NAME: PANASONIC; ICA_PARTNUM: $$1785048$$ERJ-3GSYJ102; Index PN: 684; Install: Y; Lead Style: SMT; MFG: Yageo; Material: chip; P/D_NUM: RC0402FR-071KL; Part Number: RC0402FR-071KL; Part Specific: RES 1.00K OHM 1/10W 1% 0402 SMD; Power: 1/16W; TOLERANCE: 1%; Type: resistor; VPC: 1/16W; Vendor: Yageo
R612 = PAS,R,large: ALT_SYMBOLS: 0402_1mm; CCA: 67; DigiKey: P33.2LCT-ND; Family: passive; ICA_MFR_NAME: PANASONIC; ICA_PARTNUM: $$1785048$$ERJ-3GSYJ102; Index PN: 725; Install: DNI; MFG: Panasonic; Material: chip; P/D_NUM: ERJ-2RKF33R2X; Part Number: ERJ-2RKF33R2X; Part Specific: RES 33.2 OHM 1/16W 1% 0402 SMD; Power: 1/16W; TOLERANCE: 1%; Type: resistor; VPC: 1/16W; Vendor: Panasonic
R856 = PAS,R,large: DigiKey: P200LCT-ND; Family: passive; Index PN: 1735; Lead Style: SMT; MFG: Panasonic; Material: chip; P/D_NUM: ERJ-2RKF2000X; Part Number: ERJ-2RKF2000X; Part Specific: RES SMD 200 OHM 1% 1/10W 0402; Tolerance: 1%; Type: resistor; VPC: 1/16W; Vendor: Panasonic
SW3 = EM,SW,SPDT,GT11,1x: DigiKey: CKN1784CT-ND; Family: electro/mechanical; Index PN: 1035; Install: Y; Lead Style: SMT; MFG: C&K; Part Specific: SWITCH TOGGLE SPDT ULTRAMINI SMD; Type: switch; Vendor: C&K
TP32-TP37 TP41-TP43 TP64-TP76 TP111-TP128 TP265-TP267 = BF,HOLE,PLATED,TESTPIN: Family: board feature; Index PN: 1145; Install: DNI; Lead Style: SMT; MFG: -- NOT A PART --; Type: pad pattern; Vendor: -- NOT A PART --
TP77 = BF,HOLE,PLATED,TESTPIN: DigiKey: ---; Family: board feature; Index PN: 377; Install: DNI; Lead Style: TH; MFG: -- NOT A PART --; Part Specific: HOLE_PLATED_40mil_DRILL_60mil_PAD; Type: hole,plated; Vendor: -- NOT A PART --
U26 = PROC,MICCNTL,1x,MSP430F5529IPN: DigiKey: 296-27306-1-ND; Family: processor; Index PN: 1343; Install: Y; Lead Style: SMT; MFG: Texas Instruments; P/D_NUM: MSP430F5529IPNR; Part Number: MSP430F5529IPNR; Part Specific: IC MCU 16BIT 128KB FLASH 80LQFP; Type: microcontroller; Vendor: Texas Instruments
U558 = TMP_29: DigiKey: 296-18256-1-ND; Family: logic; Index PN: 1027; Lead Style: SMT; MFG: Texas Instruments; P/D_NUM: SN74AUP1G07DCKR; Part Number: SN74AUP1G07DCKR; Part Specific: IC BUFF/DVR LOW PWR N-INV SC705  open drain; Type: buffer
J42 = EM,CONN,51P,FI-RE51S,VF_and_HF: DigiKey: 670-2149-1-ND; Family: electro/mechanical; Index PN: 1629; Lead Style: SMT; MFG: JAE; Part Specific: 51 Position Receptacle Connector 0.020in (0.50mm) Surface Mount Gold; Pin Cnt: 51; Type: connector; Vendor: JAE
J44 = EM,CONN,51P,FI-RE51S,VF_and_HF: DigiKey: 670-2149-1-ND; Family: electro/mechanical; Index PN: 1629; Install: Y; Lead Style: SMT; MFG: JAE; Part Specific: 51 Position Receptacle Connector 0.020in (0.50mm) Surface Mount Gold; Pin Cnt: 51; Type: connector; Vendor: JAE
J62 = EM,HDR,2P,1R,1x,B2B_EH,inline: DigiKey: 455-1611-ND; Family: electro/mechanical; Index PN: 1297; Lead Style: TH; MFG: JST; P/D_NUM: B2B-EH-A(LF)(SN); Part Number: B2B-EH-A(LF)(SN); Part Specific: CONN HEADER EH TOP 2POS 2.5MM; Pin Cnt: 3; Pin Spacing: 2.5MM; Row Cnt: 1; Type: header; Vendor: JST
J500 = EM,CONN,51P,FI-RE51S,VF_and_HF: DigiKey: 670-1206-1-ND; Family: electro/mechanical; Index PN: 1668; Lead Style: SMT; MFG: JAE; Part Specific: 51 Position Receptacle Connector 0.020in (0.50mm) Surface Mount Right Angle Gold; Pin Cnt: 51; Type: connector; Vendor: JAE
R533-R540 R546-R548 R550 = PAS,R,large: ALT_SYMBOLS: 0402_1mm; CCA: 62; DigiKey: P0.0JCT-ND; Family: passive; ICA_MFR_NAME: PANASONIC; ICA_PARTNUM: $$1785048$$ERJ-3GSYJ102; Index PN: 687; Install: Y; Lead Style: SMT; MFG: Panasonic; Material: chip; P/D_NUM: ERJ-2GE0R00X; Part Number: ERJ-2GE0R00X; Part Specific: RES 0.0 OHM 1/16W 0402 SMD; Power: 1/16W; Type: resistor; VPC: 1/16W; Vendor: Panasonic
R626 = PAS,R,large: ALT_SYMBOLS: 0402_1mm; DigiKey: 311-22.0LRCT-ND; Family: passive; Index PN: 1215; Lead Style: SMT; MFG: Yageo; Material: chip; P/D_NUM: RC0402FR-0722RL; Part Number: RC0402FR-0722RL; Part Specific: RES 22.0 OHM 1/16W 1% 0402 SMD; Tolerance: 1%; Type: resistor; VPC: 1/16W; Vendor: Yageo
TP46-TP56 TP212-TP216 = EM,TERM,TESTPOINT: DigiKey: ---; Family: board feature; Index PN: 1498; Install: DNI; Lead Style: TH; MFG: -- NOT A PART --; Part Specific: HOLE PLATED 48mil pad 28mil drill; Type: hole,plated; Vendor: -- NOT A PART --
Z_BOARD1 = DLP055_MECH: MFG: ANY
Z_BOARD2 = DLP064_MECH: MFG: ANY
Z_MECH1 = JF08R0R051020UA_MECH: MFG: JAE ELECTRONICS INC
Z_MECH2 = JF08R0R051020UA_MECH: CONN JUMPER SHORTING GOLD FLASH; MFG: Sullins Connector Solutions; Manufacturer: Sullins Connector Solutions

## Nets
GND: C511.2 C514.2 C515.2 C519.2 C520.1 C521.2 C528.1 C529.2 C530.1 C531.1 C547.2 C548.1 C549.2 C585.2 C622.2 C623.2 C624.2 C625.2 J42.5 J42.6 J42.7 J42.9 J42.12 J42.15 J42.18 J42.21 J42.24 J42.27 J42.30 J42.33 J42.36 J42.39 J42.42 J42.45 J42.48 J42.52(GND) J42.53(GND) J42.54(GND) J42.55(GND) J42.56(GND) J42.57(GND) J42.58(GND) J42.59(GND) J42.60(GND) J42.61(GND) J42.62(GND) J42.63(GND) J44.5 J44.6 J44.7 J44.8 J44.10 J44.13 J44.16 J44.19 J44.22 J44.25 J44.27 J44.33 J44.39 J44.43 J44.45 J44.48 J44.52(GND) J44.53(GND) J44.54(GND) J44.55(GND) J44.56(GND) J44.57(GND) J44.58(GND) J44.59(GND) J44.60(GND) J44.61(GND) J44.62(GND) J44.63(GND) J51.3 J62.2 J69.9 J69.10 J69.14 J70.9(P9) J83.4(GND) J83.5(C1) J83.6(C2) J85.3 J96.12 J500.1 J500.3 J500.5 J500.7 J500.9 J500.11 J500.13 J500.15 J500.17 J500.19 J500.21 J500.23 J500.25 J500.27 J500.29 J500.31 J500.33 J500.35 J500.37 J500.39 J500.41 J500.43 J500.45 J500.47 J500.49 J500.51 J500.52(GND) J500.53(GND) J500.54(GND) J500.55(GND) J500.56(GND) J500.57(GND) J500.58(GND) J500.59(GND) J500.60(GND) J500.61(GND) J500.62(GND) J500.63(GND) R155.1(N1) R586.1(N1) R593.1(N1) R594.1(N1) R595.1(N1) R629.2(N2) U17.4(GND) U26.14(AVSS1) U26.19(DVSS1) U26.49(DVSS2) U26.61(VSSU) U26.68(AVSS2) U27.2(GND) U40.3(GND) U42.3(GND) U501.4(GND) U558.3(GND) U559.2(GND) U560.1(A0) U560.2(A1) U560.3(A2) U560.4(GND) U561.2(GND) U562.4(VSSD) U562.17(VSSD) U562.20(VSSD) U562.24(VSSA) U562.33(PAD) U563.3(GND) U564.3(GND) ; also on sheet 6 7 8 9 10 11 12 15 16 17 18 19 20 21 22 23 25 26
P5V: J60.1 ; also on sheet 10 15 25
P5V_FP_FE: J42.1 J42.2 J42.3 J42.4 J60.2
VBUS: TP76.1(P1) U26.65(VBUS)
3D_LR: J61.2 J62.1 TP212.1(P1)
3D_REF: J44.3 ; also on sheet 26
40MHz_CLK0: J500.26 ; also on sheet 18
AFE_ARSTZ: J44.47 ; also on sheet 26
AFE_CLK: J44.44 R626.2(N2)
AFE_CLK_T: R626.1(N1) ; also on sheet 26
AFE_IRQ: R627.1(N1) ; also on sheet 26
ALF_CSYNC: J44.42 TP51.1(P1) ; also on sheet 26
ALF_HSYNC: J44.41 TP52.1(P1) ; also on sheet 26
ALF_VSYNC: J44.40 TP53.1(P1) ; also on sheet 26
BT656_CLK: J44.26 J500.10 ; also on sheet 20 26
BT656_DATA_0: J44.38 R536.2(N2) R537.2(N2) ; also on sheet 20 26
BT656_DATA_0_M: J500.24 R537.1(N1)
BT656_DATA_0_S: J500.28 R536.1(N1)
BT656_DATA_1: J44.37 R535.2(N2) R538.2(N2) ; also on sheet 20 26
BT656_DATA_1_M: J500.22 R538.1(N1)
BT656_DATA_1_S: J500.30 R535.1(N1)
BT656_DATA_2: J44.36 J500.46 ; also on sheet 20 26
BT656_DATA_3: J44.35 J500.44 ; also on sheet 20 26
BT656_DATA_4: J44.34 ; also on sheet 20 26
BT656_DATA_5: J44.32 ; also on sheet 20 26
BT656_DATA_6: J44.31 ; also on sheet 20 26
BT656_DATA_7: J44.30 ; also on sheet 20 26
BT656_DATA_8: J44.29 J500.14 ; also on sheet 20 26
BT656_DATA_9: J44.28 J500.12 ; also on sheet 20 26
CY_GPIO_0: U42.2(A) U562.25(GPIO_0)
CY_GPIO_0_DRV: R226.2(N2) U42.4(Y)
CY_GPIO_0_LED: D10.1(CATHODE) R226.1(N1)
CY_GPIO_1: U40.2(A) U562.26(GPIO_1)
CY_GPIO_1_DRV: R218.2(N2) U40.4(Y)
CY_GPIO_1_LED: D53.1(CATHODE) R218.1(N1)
CY_GPIO_2: J96.3 U562.27(SCB0_1/GPIO_2)
CY_GPIO_5: J96.4 U562.30(SCB0_4/GPIO_5)
CY_GPIO_6: J96.5 U562.31(GPIO_6) U564.2(A)
CY_GPIO_6_BUF: R217.1(N1) U564.4(Y)
CY_GPIO_7: J96.6 U562.32(GPIO_7) U563.2(A)
CY_GPIO_7_BUF: R212.1(N1) U563.4(Y)
CY_GPIO_8: R154.2(N2) TP129.1(P1) U562.2(SCB0_0/GPIO_8)
CY_GPIO_9: J84.1 R219.2(N2) U562.3(SCB0_5/GPIO_9)
CY_GPIO_10: J75.2(P2) U562.5(SCB1_0/GPIO_10)
CY_GPIO_11: J75.4(P4) U562.6(SCB1_1/GPIO_11)
CY_GPIO_12: J75.6(P6) J96.7 U562.7(SCB1_2/GPIO_12)
CY_GPIO_13: J96.8 R211.1(N1) U562.8(SCB1_3/GPIO_13)
CY_GPIO_13_T: J75.8(P8) R211.2(N2)
CY_GPIO_14: J75.10(P10) J96.9 U562.9(SCB1_4/GPIO_14)
CY_GPIO_16: TP145.1(P1) U562.13(GPIO_16)
CY_GPIO_17: J96.10 U562.21(GPIO_17)
CY_GPIO_18: J96.11 R222.2(N2)
CY_GPIO_18_T: R222.1(N1) U562.22(GPIO_18)
CY_IIC0_OE: J84.2 R155.2(N2) R219.1(N1) U561.6(OE)
CY_IIC0_SCL: R605.1(N1) U27.8(B1) U560.6(SCL) U561.8(B1) U562.28(SCB0_2/GPIO_3)
CY_IIC0_SDA: R623.1(N1) U27.1(B2) U560.5(SDA) U561.1(B2) U562.29(SCB0_3/GPIO_4)
CY_IIC_MSP_OE: R154.1(N1) U27.6(OE)
CY_MSP_SCL: U26.38(P3.1/UCB0SOMI/UCB0SCL) U27.5(A1)
CY_MSP_SDA: U26.37(P3.0/UCB0SIMO/UCB0SDA) U27.4(A2)
CY_SUSPEND: TP144.1(P1) U562.11(SUSPEND)
CY_VBUS: C625.1 J83.1(VBUS) U562.19(VBUS)
CY_VCCD: C624.1 U562.16(VCCD)
CY_WAKEUP: TP147.1(P1) U562.12(WAKEUP)
DAO_CLKOUT: J500.42 ; also on sheet 20
DAO_DO_0: J500.38 ; also on sheet 20
DAO_DO_1: J500.40 ; also on sheet 20
EEPROM_WP: J72.2 U560.7(WP)
EXT_I2C_EN: J52.2 R586.2(N2) U559.6(OE)
EXT_I2CPWR: C511.1 F1.1(N1) J51.4
EXT_SCL: J51.2 R863.2(N2) U17.6(IO2)
EXT_SCL_T: R861.1(N1) R863.1(N1) U559.8(B1)
EXT_SDA: J51.1 R864.2(N2) U17.3(IO1)
EXT_SDA_T: R862.1(N1) R864.1(N1) U559.1(B2)
FE_3D_LR: J42.11 J44.51 J61.1 ; also on sheet 15 20
FIELD: J44.4 ; also on sheet 26
FP_A_A_n: J42.47 ; also on sheet 26
FP_A_A_p: J42.46 ; also on sheet 26
FP_A_B_n: J42.44 ; also on sheet 26
FP_A_B_p: J42.43 ; also on sheet 26
FP_A_C_n: J42.41 ; also on sheet 26
FP_A_C_p: J42.40 ; also on sheet 26
FP_A_CLK_n: J42.32 ; also on sheet 26
FP_A_CLK_p: J42.31 ; also on sheet 26
FP_A_D_n: J42.38 ; also on sheet 26
FP_A_D_p: J42.37 ; also on sheet 26
FP_A_E_n: J42.35 ; also on sheet 26
FP_A_E_p: J42.34 ; also on sheet 26
FP_B_A_n: J42.26 ; also on sheet 26
FP_B_A_p: J42.25 ; also on sheet 26
FP_B_B_n: J42.23 ; also on sheet 26
FP_B_B_p: J42.22 ; also on sheet 26
FP_B_C_n: J42.20 ; also on sheet 26
FP_B_C_p: J42.19 ; also on sheet 26
FP_B_CLK_n: J42.29 ; also on sheet 26
FP_B_CLK_p: J42.28 ; also on sheet 26
FP_B_D_n: J42.17 ; also on sheet 26
FP_B_D_p: J42.16 ; also on sheet 26
FP_B_E_n: J42.14 ; also on sheet 26
FP_B_E_p: J42.13 ; also on sheet 26
HBT_CLKOUT: J500.8 ; also on sheet 20
HBT_DO: J500.6 ; also on sheet 20
HDMI_CEC: J42.49 TP47.1(P1) ; also on sheet 15 20
IIC0_SCL: J53.1 R585.2(N2) U559.5(A1) U561.5(A1) ; also on sheet 15 18 19 26
IIC0_SDA: J54.1 R599.2(N2) U559.4(A2) U561.4(A2) ; also on sheet 15 18 19 26
IIC_BUSY: J42.51 TP46.1(P1) TP146.1(P1) U26.34(P2.5/TA2.2) U562.10(SCB1_5/GPIO_15) ; also on sheet 15 20
IIC_SCL_FP: J42.10 ; also on sheet 26
IIC_SDA_FP: J42.8 ; also on sheet 26
J9_SP1: J44.1 TP56.1(P1)
J9_SP2: J44.2 TP55.1(P1)
J9_SP9: J44.9 TP54.1(P1)
J9_SP46: J44.46 TP50.1(P1)
J9_SP49: J44.49 TP49.1(P1)
J9_SP50: J44.50 TP48.1(P1)
KEYPD_11: J69.11 R857.2(N2)
KEYPD_12: J69.12 R858.2(N2)
KEYPD_13: J69.13 R152.2(N2)
KEYPD_DOWN: J69.4 R597.1(N1) U26.23(P1.2/TA0.1)
KEYPD_LED_HOT: R857.1(N1) U26.27(P1.6/TA1CLK/CBOUT)
KEYPD_LED_LMP: R858.1(N1) U26.28(P1.7/TA1.0)
KEYPD_LED_PWR: R152.1(N1) U26.29(P2.0/TA1.1)
KEYPD_LEFT: J69.5 R610.1(N1) U26.24(P1.3/TA0.2)
KEYPD_P3P3V: J69.1 J69.8 R612.2(N2)
KEYPD_PWR: J69.7 R611.1(N1) U26.26(P1.5/TA0.4)
KEYPD_RIGHT: J69.6 R598.1(N1) U26.25(P1.4/TA0.3)
KEYPD_SEL: J69.2 R596.1(N1) U26.21(P1.0/TA0CLK/ACLK)
KEYPD_UP: J69.3 R609.1(N1) U26.22(P1.1/TA0.0)
MSP_IIC0_SCL: J53.2 R585.1(N1) U26.47(P4.2/PM_UCB1SOMI/PM_UCB1SCL)
MSP_IIC0_SDA: J54.2 R599.1(N1) U26.46(P4.1/PM_UCB1SIMO/PM_UCB1SDA)
MSP_LED2: D52.1(CATHODE) R856.2(N2)
MSP_LED2_DRVR: R856.1(N1) U558.4(Y)
MSP_LED2_ONz: U26.56(P5.7/TB0.1) U558.2(A)
MSP_PROJ_ON: R608.1(N1) ; also on sheet 21
MSP_RSTNMI: J70.11(P11) R592.2(N2) U26.76(R~{ST}\\/NMI/SBWTDIO)
MSP_V18: C531.2 U26.67(V18)
MSP_VCORE: C521.1 U26.20(VCORE)
MSPIF_VCC1: J70.4(P4) R606.2(N2)
MSPIF_VCC2: J70.2(P2) R607.2(N2)
MSPJTAG_TCK: J70.7(P7) U26.75(PJ.3/TCK)
MSPJTAG_TDI: J70.3(P3) U26.73(PJ.1/TDI/TCLK)
MSPJTAG_TDO: J70.1(P1) U26.72(PJ.0/TDO)
MSPJTAG_TMS: J70.5(P5) U26.74(PJ.2/TMS)
P2.1: TP64.1(P1) U26.30(P2.1/TA1.2)
P2.2: TP66.1(P1) U26.31(P2.2/TA2CLK/SMCLK)
P2.3: TP65.1(P1) U26.32(P2.3/TA2.0)
P2.4: TP67.1(P1) U26.33(P2.4/TA2.1)
P2.6: R608.2(N2) U26.35(P2.6/RTCCLK/DMAE0)
P2.7: TP68.1(P1) U26.36(P2.7/UCB0STE/UCA0CLK)
P3.2: TP112.1(P1) U26.39(P3.2/UCB0CLK/UCA0STE)
P3.3: TP111.1(P1) U26.40(P3.3/UCA0TXD/UCA0SIMO)
P3.4: TP113.1(P1) U26.41(P3.4/UCA0RXD/UCA0SOMI)
P3.6: TP114.1(P1) U26.43(P3.6/TB0.6)
P3.7: TP115.1(P1) U26.44(P3.7/TB0OUTH/SVMOUT)
P3P3V: C514.1 J96.2 U559.3(VCCA) ; also on sheet 6 7 8 9 10 11 12 15 16 18 19 20 21 22 25 26
P3P3V_SB: C515.1 C519.1 C520.2 C528.2 C529.1 C530.2 C547.1 C548.2 C549.1 C622.1 C623.1 D10.2(ANODE) D52.2(ANODE) D53.2(ANODE) F1.2(N2) J52.1 J72.1 J85.1 J96.1 R592.1(N1) R596.2(N2) R597.2(N2) R598.2(N2) R605.2(N2) R606.1(N1) R607.1(N1) R609.2(N2) R610.2(N2) R611.2(N2) R612.1(N1) R623.2(N2) R628.2(N2) R853.2(N2) R854.2(N2) R855.2(N2) R861.2(N2) R862.2(N2) U17.1(VCC) U26.11(AVCC1) U26.18(DVCC1) U26.50(DVCC2) U27.3(VCCA) U27.7(VCCB) U40.5(PWR) U42.5(PWR) U558.5(PWR) U559.7(VCCB) U560.8(VCC) U561.3(VCCA) U561.7(VCCB) U562.1(VDDD) U562.23(VDDD) U563.5(PWR) U564.5(PWR) ; also on sheet 7 19 21
P4.0: TP116.1(P1) U26.45(P4.0/PM_UCB1STE/PM_UCA1CLK)
P4.3: TP117.1(P1) U26.48(P4.3/PM_UCB1CLK/PM_UCA1STE)
P4.4: TP118.1(P1) U26.51(P4.4/PM_UCA1TXD/PM_UCA1SIMO)
P4.5: TP119.1(P1) U26.52(P4.5/PM_UCA1RXD/PM_UCA1SOMI)
P4.6: TP120.1(P1) U26.53(P4.6/PM_NONE)
P4.7: TP121.1(P1) U26.54(P4.7/PM_NONE)
P5.0: TP267.1(P1) U26.9(P5.0/A8/VREF+/VeREF+)
P5.1: TP37.1(P1) U26.10(P5.1/A9/VREF-/VeREF-)
P5.2: TP75.1(P1) U26.69(P5.2/XT2IN)
P5.3: TP71.1(P1) U26.70(P5.3/XT2OUT)
P5.4: TP36.1(P1) U26.12(P5.4/XIN)
P5.5: TP35.1(P1) U26.13(P5.5/XOUT)
P5.6: TP122.1(P1) U26.55(P5.6/TB0.0)
P6.0: TP74.1(P1) U26.77(P6.0/CB0/A0)
P6.1: TP70.1(P1) U26.78(P6.1/CB1/A1)
P6.2: TP73.1(P1) U26.79(P6.2/CB2/A2)
P6.3: TP69.1(P1) U26.80(P6.3/CB3/A3)
P6.4: J57.1 R593.2(N2) U26.1(P6.4/CB4/A4)
P6.4_PU: J57.2 R853.1(N1)
P6.5: J56.1 R594.2(N2) U26.2(P6.5/CB5/A5)
P6.5_PU: J56.2 R854.1(N1)
P6.6: J55.1 R595.2(N2) U26.3(P6.6/CB6/A6)
P6.6_PU: J55.2 R855.1(N1)
P6.7: TP43.1(P1) U26.4(P6.7/CB7/A7)
P7.0: TP42.1(P1) U26.5(P7.0/CB8/A12)
P7.1: TP41.1(P1) U26.6(P7.1/CB9/A13)
P7.2: TP265.1(P1) U26.7(P7.2/CB10/A14)
P7.3: TP266.1(P1) U26.8(P7.3/CB11/A15)
P7.4: TP123.1(P1) U26.57(P7.4/TB0.2)
P7.5: TP124.1(P1) U26.58(P7.5/TB0.3)
P7.6: TP125.1(P1) U26.59(P7.6/TB0.4)
P7.7: TP126.1(P1) U26.60(P7.7/TB0CLK/MCLK)
P8.0: TP34.1(P1) U26.15(P8.0)
P8.1: TP33.1(P1) U26.16(P8.1)
P8.2: TP32.1(P1) U26.17(P8.2)
PDATA_C0: J44.24 ; also on sheet 26
PDATA_C1: J44.23 ; also on sheet 26
PDATA_C2: J44.21 ; also on sheet 26
PDATA_C3: J44.20 ; also on sheet 26
PDATA_C4: J44.18 ; also on sheet 26
PDATA_C5: J44.17 ; also on sheet 26
PDATA_C6: J44.15 ; also on sheet 26
PDATA_C7: J44.14 ; also on sheet 26
PDATA_C8: J44.12 ; also on sheet 26
PDATA_C9: J44.11 ; also on sheet 26
PU.0: TP127.1(P1) U26.62(PU.0/DP)
PU.1: TP72.1(P1) U26.64(PU.1/DM)
PUR: TP128.1(P1) U26.63(PUR)
SPI2_CIPO: J500.36 ; also on sheet 20 26
SPI2_CLK: R534.2(N2) R539.2(N2) ; also on sheet 20 26
SPI2_CLK_M: J500.20 R539.1(N1)
SPI2_CLK_S: J500.32 R534.1(N1)
SPI2_COPI: J500.16 ; also on sheet 20 26
SPI2_CSZ_0: R533.2(N2) R540.2(N2) ; also on sheet 20 26
SPI2_CSZ_0_M: J500.18 R540.1(N1)
SPI2_CSZ_0_S: J500.34 R533.1(N1)
SPI2_CSZ_1: R546.2(N2) R550.2(N2) ; also on sheet 20 26
SPI2_CSZ_1_M: J500.2 R550.1(N1) TP215.1(P1)
SPI2_CSZ_1_S: J500.50 R546.1(N1) TP214.1(P1)
SPI2_CSZ_2: R547.2(N2) R548.2(N2) ; also on sheet 20 26
SPI2_CSZ_2_M: J500.4 R548.1(N1) TP216.1(P1)
SPI2_CSZ_2_S: J500.48 R547.1(N1) TP213.1(P1)
STATUS_INT: J42.50 R627.2(N2)
SW_ONOFF: C585.1 J85.2 R212.2(N2) SW3.2 U26.42(P3.5/TB0.5)
SW_ONOFF_PD: R629.1(N1) SW3.1 SW3.4
SW_ONOFF_PU: R628.1(N1) SW3.3 SW3.6
SW_PROJ_ON: R217.2(N2) ; also on sheet 21
TCK: J75.7(P7) ; also on sheet 18
TDI: J75.3(P3) ; also on sheet 18
TDO1: J75.1(P1) ; also on sheet 18
TEST_SBWTCK: J70.8(P8) U26.71(TEST/SBWTCK)
TMS1: J75.5(P5) ; also on sheet 18
TRSTZ_IN: J75.9(P9) ; also on sheet 18
USBDM: J83.2(DM) U501.5(IO2) U562.15(USBDM)
USBDP: J83.3(DP) U501.3(IO1) U562.14(USBDP)
VUSB: TP77.1(P1) U26.66(VUSB)

Not connected (* = marked no-connect by the designer): J70 6(P6)* 10(P10)* 12(P12)* 13(P13)* 14(P14)*; U17 2(NC2)* 5(NC5)*; U40 1*; U42 1*; U501 1(NC1)* 2(NC2)*; U558 1*; U562 18(nXRES)*; U563 1*; U564 1*

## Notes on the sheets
sheet 1
- (C) COPYRIGHT 2020
         Texas Instruments
        All Rights Reserved
sheet 2
- REVISION HISTORY
- NOTE:Below are the changes from reviosn A to B
- 1.Update TITLE from “DLPC7540 FORMATTER BOARD” to “DLPC7540EVM FORMATTER BOARD”.
  2.Update Drawing No. to DLP055 on all schematic pages.
  3.Remove note of “PRELIMINARY” throughout all schematic pages
  4.All mentions of “DLPC6540” should be changed to “DLPC7540"
  5.For part number UMK105BJ104KV-F that is covered by reference designators C321,C687,C688,C689,C690,C695,C696, update the Package parameter from 0603 to 0402. This discrepancy causes the 0603 to erroneously be inserted to BOM
  6.Add the INSTALL parameter to all parts that are listed in the file “parts to add INSTALL parameter.XLSX”.
  7.Change from DNI to INSTALL YES all parts that are listed in the file “Change from DNI to Install YES.XLSX”.
  8.For the part in reference designators TP227,TP228,TP229,TP230,TP231,TP232,TP233,TP234,TP235,TP236,TP237,TP238,TP239,TP240,TP241,TP242,TP243,TP244,TP245,TP246,TP247,TP248,TP249,TP272,TP273,TP274,TP275,TP276,TP277,TP278,TP279,TP280,TP281,TP282,TP283
  update the INSTALL parameter that was created in step 9 to DNI.
  9.Update manufacturer part number for U525 and U526 to LM3881MM/NOPB.
  10.Update manufacturer part number for U555, U556 and U557 to DLPA100PT.
  11.On Title Page:
  a.	“D3 – VIN (19V) (high = led on)” should be changed to “D3 – VIN (12V) (high = led on)” under STATUS LEDs section.
  b.	Remove note “PRELIMINARY – UNTESTED ENGINEERING RELEASE ONLY”
  c.	Confirm that sheet designations in index are correct after sheet numbering has been completed.
  12.On Block Diagram page: Replace block diagram with visio file provided.
  13.On DLPC FPDLink/Parallel In page:
  a.	Remove compatible part numbers note inside U15B.
  b.	Move “Place jumper across pins 1 & 2 to enabe IIC0.” and “Place jumper across pins 2 & 3 to enable IIC1” notes so that they do not overlap sheet grid or any other drawings.
  c.	Correct typo in “Place jumper across pins 1 & 2 to enabe IIC0.” to “Place jumper across pins 1 & 2 to enable IIC0”.
  14.On Actuator Driver page:
  a.	Remove note for Actuator Option #2
  b.	Make R134, R135, R136 and R137 install “Y”.
  c.	Change “ECD Actuator I/F” to “External Actuator Driver Board I/F”.
  15.On VIN & POWER SEQ page:
  a.	Redesign all circuits on page so that they follow how it is designed on Page 5 of 7540_PMD_BOARD.DSN. Make sure that any nets referring to VCORE_EN are kept as P1P15V_EN and P3P3V_STBY are kept as P3P3V_SB.
   Note that one of the changes is that VIN of TPS54327 should end up coming from P12V_VIN and not P12V. Feel free to contact us if there are questions regarding this request.
  b.	Keep the net names consistent with existing DLPC7540_EVM.DSN when redesigning based on 7540_PMD_BOARD.DSN. Follow this convention for keeping net names.
  Net name from 7540_PMD_BOARD.DSN	Net name to maintain in DLPC7540_EVM.DSN
  POWERGOOD	PMIC_POWERGOOD
  VCORE_EN	P1P15V_EN
  P3P3V_STDBY	P3P3V_SB
  VCORE_PG	P1P15V_PG
  c.	Remove note of changes to P3P3V_SB.
  d.	Remove note of VCORE_EN change
  e.	Update note from “DLPC7541 SUPPLY SEQUENCING” to “DLPC7540 SUPPLY SEQUENCING”
  f.	Remove DNI note from R832 (referring to R135 if looking at design from page 5 at 7540_PMD_BOARD.DSN). This resistor needs to be populated
  g.	R830 should be DNI (referring to R94 if looking at design from page 5 at 7540_PMD_BOARD.DSN). It is currently only marked as DNI with a note. This part needs to have the Install property added and have it marked as DNI so that the part is correctly marked as DNI in BOM.
  h.	C801 should be DNI (referring to C50 if looking at design from page 5 at 7540_PMD_BOARD.DSN). It is currently only marked as DNI with a note. This part needs to have the Install property added and have it marked as DNI so that the part is correctly marked as DNI in BOM.
  i.	C820 should be DNI (referring to C111 if looking at design from page 5 at 7540_PMD_BOARD.DSN). It is currently only marked as DNI with a note. This part needs to have the Install property added and have it marked as DNI so that the part is correctly marked as DNI in BOM.
  16.On DLPA100 #0 page:
  a.	Delete “DNI – For Validation Only” note.
  b.	Remove note “Diodes Inc DMTH6009K3-13 can be used for 5V if cooled”
  c.	Delete D29 from design.
  d.	Change note J515 from “CW1 MOTOR DRIVE” to “CW0 MOTOR DRIVE”
  17.On DLPA100 #1 page:
  a.	Change note J519 from “CW2 MOTOR DRIVE” to “CW1 MOTOR DRIVE”
  18.On DLPA100 #2 page:
  a.	Change note J523 from “CW3 MOTOR DRIVE” to “CW2 MOTOR DRIVE”
  19.Add a Hardware Page sheet where you place:
  a.	PCB component which part number is “DLP055”; Manufacturer is “ANY”; Description is “Printed Circuit Board, DLP055”; Quantity is 1
  b.	PCB component which part number is “DLP064”; Manufacturer is “ANY”; Description is “Printed Circuit Board, DLP064”; Quantity is 1
  c.	Mechanical part which part number is “JF08R0R051020UA”; Manufacturer is “JAE Electronics”; Description is “CABLE ASSY HI SPEED 51POS 20CM”; Quantity is 1
  d.	See image below for an example of how components show up on Hardware Page
  20.Replace any text within terms that say “MISO” with “CIPO” throughout the schematic (ie. replace “SPI1_MISO” with “SPI1_CIPO”)
  21.Replace any text within terms that say “MOSI” with “COPI” throughout the schematic (ie. replace “SPI1_MOSI” with “SPI1_COPI”)
  22.Change any notes or net names from “master” to “primary”.
  23.Change any notes or net names from “slave” to “secondary”.
  24.Place note “For Texas Instruments Development Only” within the dotted box for the REALVIEW ICE JTAG I/F in the DLPC MISC page. Move the text “REALVIEW ICE JTAG I/F” so that it is not crossing the cutoff by the dotted box.
  25.Add note “For Texas Instruments Development Only” on top of following schematic pages:
  a.	Ballast Connection
  b.	Cypress
  c.	Keypad, MSP430
  26.Move J42 that’s currently in “DLPC FPDlink/Parallel In” page and everything enclosed in red marking to a new schematic page to be named as . Place a note on top of this new schematic page indicating “For Texas Instruments Development Only”. Link back to appropriate nodes with off page interconnects as necessary.
  27.Move J44 that’s currently in “DLPC FPDlink/Parallel In” page and everything enclosed in red marking to the same schematic page created in previous step.
  Link back to appropriate nodes with off page interconnects as necessary.
  28.Move J500 that’s currently in “DLPC FPDlink/Parallel In” page and everything enclosed in red marking to the same schematic page created in the two previous steps. Link back to appropriate nodes with off page interconnects as necessary.
  29.Correct text in Keypad, MSP430 page from “MPS430 PROGRAM & DEBUG” to “MSP430 PROGRAM & DEBUG”
  30.On DLPC VX1 Input Interface page
  a.Delete note regarding Parallel & FPDlink Interfaces and floating ground symbol.
  31.D3 Notes removed from Title page.
  32.DNI added for U500,U502,U503
  33.Update manufacturer part number for X1  to 7V-40.000MDDE-T
  34.Update manufacturer part number for X2  to 7V-38.000MAAV-T
  35.Update manufacturer part number for Q11  to NTD14N03RT4G
- NOTE:Below are the changes from reviosn B to C
- 1.Update manufacturer part number for C756,C757,C777,C778,C791,C792 to CL10A224KB8NNNC
  2.Update manufacturer part number for C18,C764,C765,C766,C770,C771,C779,C783,C784,C785,C793,C797,C798,C799,C801,C814,C815,C820 to CL21A226MAYNNNE
  3.Update manufacturer part number for C752,C753,C754,C755,C773,C774,C775,C776,C787,C788,C789,C790 to CL21B334KBFNFNE
  4.Update manufacturer part number for U15 to DLPC7540ZDC
  5.Update manufacturer part number for C317 to EMK105B7153KV-F
  6.Update manufacturer part number for U59 to TPS259260DRCR
  7.Mech part SPC02SYAN added
- (C) COPYRIGHT 2020
         Texas Instruments
        All Rights Reserved
sheet 3
- For Texas Instruments Development Only
- DUAL ASIC Connection
- <HBT_DI_0>
- <HBT_CLKIN_0>
- <SEQ_SYNC>
- <EF_SYNC/DA_SYNC>
- <EF_SYNC/DA_SYNC>
- <SEQ_SYNC>
- <DAO_DI_0>
- <DAO_DI_1>
- <DAO_CLKIN>
- (C) COPYRIGHT 2020
         Texas Instruments
        All Rights Reserved
sheet 4
- For Texas Instruments Development Only
- DEVASYS CONNECTION
- JTAG BOUNDARY SCAN
- CY7C65215 is used for test and
  validation configuration & control.
- SCB0 configured as IIC Primary (Mode 5)
  SCB1 configured as IIC Primary (Mode 5)
- (C) COPYRIGHT 2020
         Texas Instruments
        All Rights Reserved
sheet 5
- For Texas Instruments Development Only
- MSP430 PROGRAM & DEBUG
- KEYBOARD INTERFACE
- (C) COPYRIGHT 2020
         Texas Instruments
        All Rights Reserved
